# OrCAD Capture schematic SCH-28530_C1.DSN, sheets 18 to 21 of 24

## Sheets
18 18 PCIe: size C
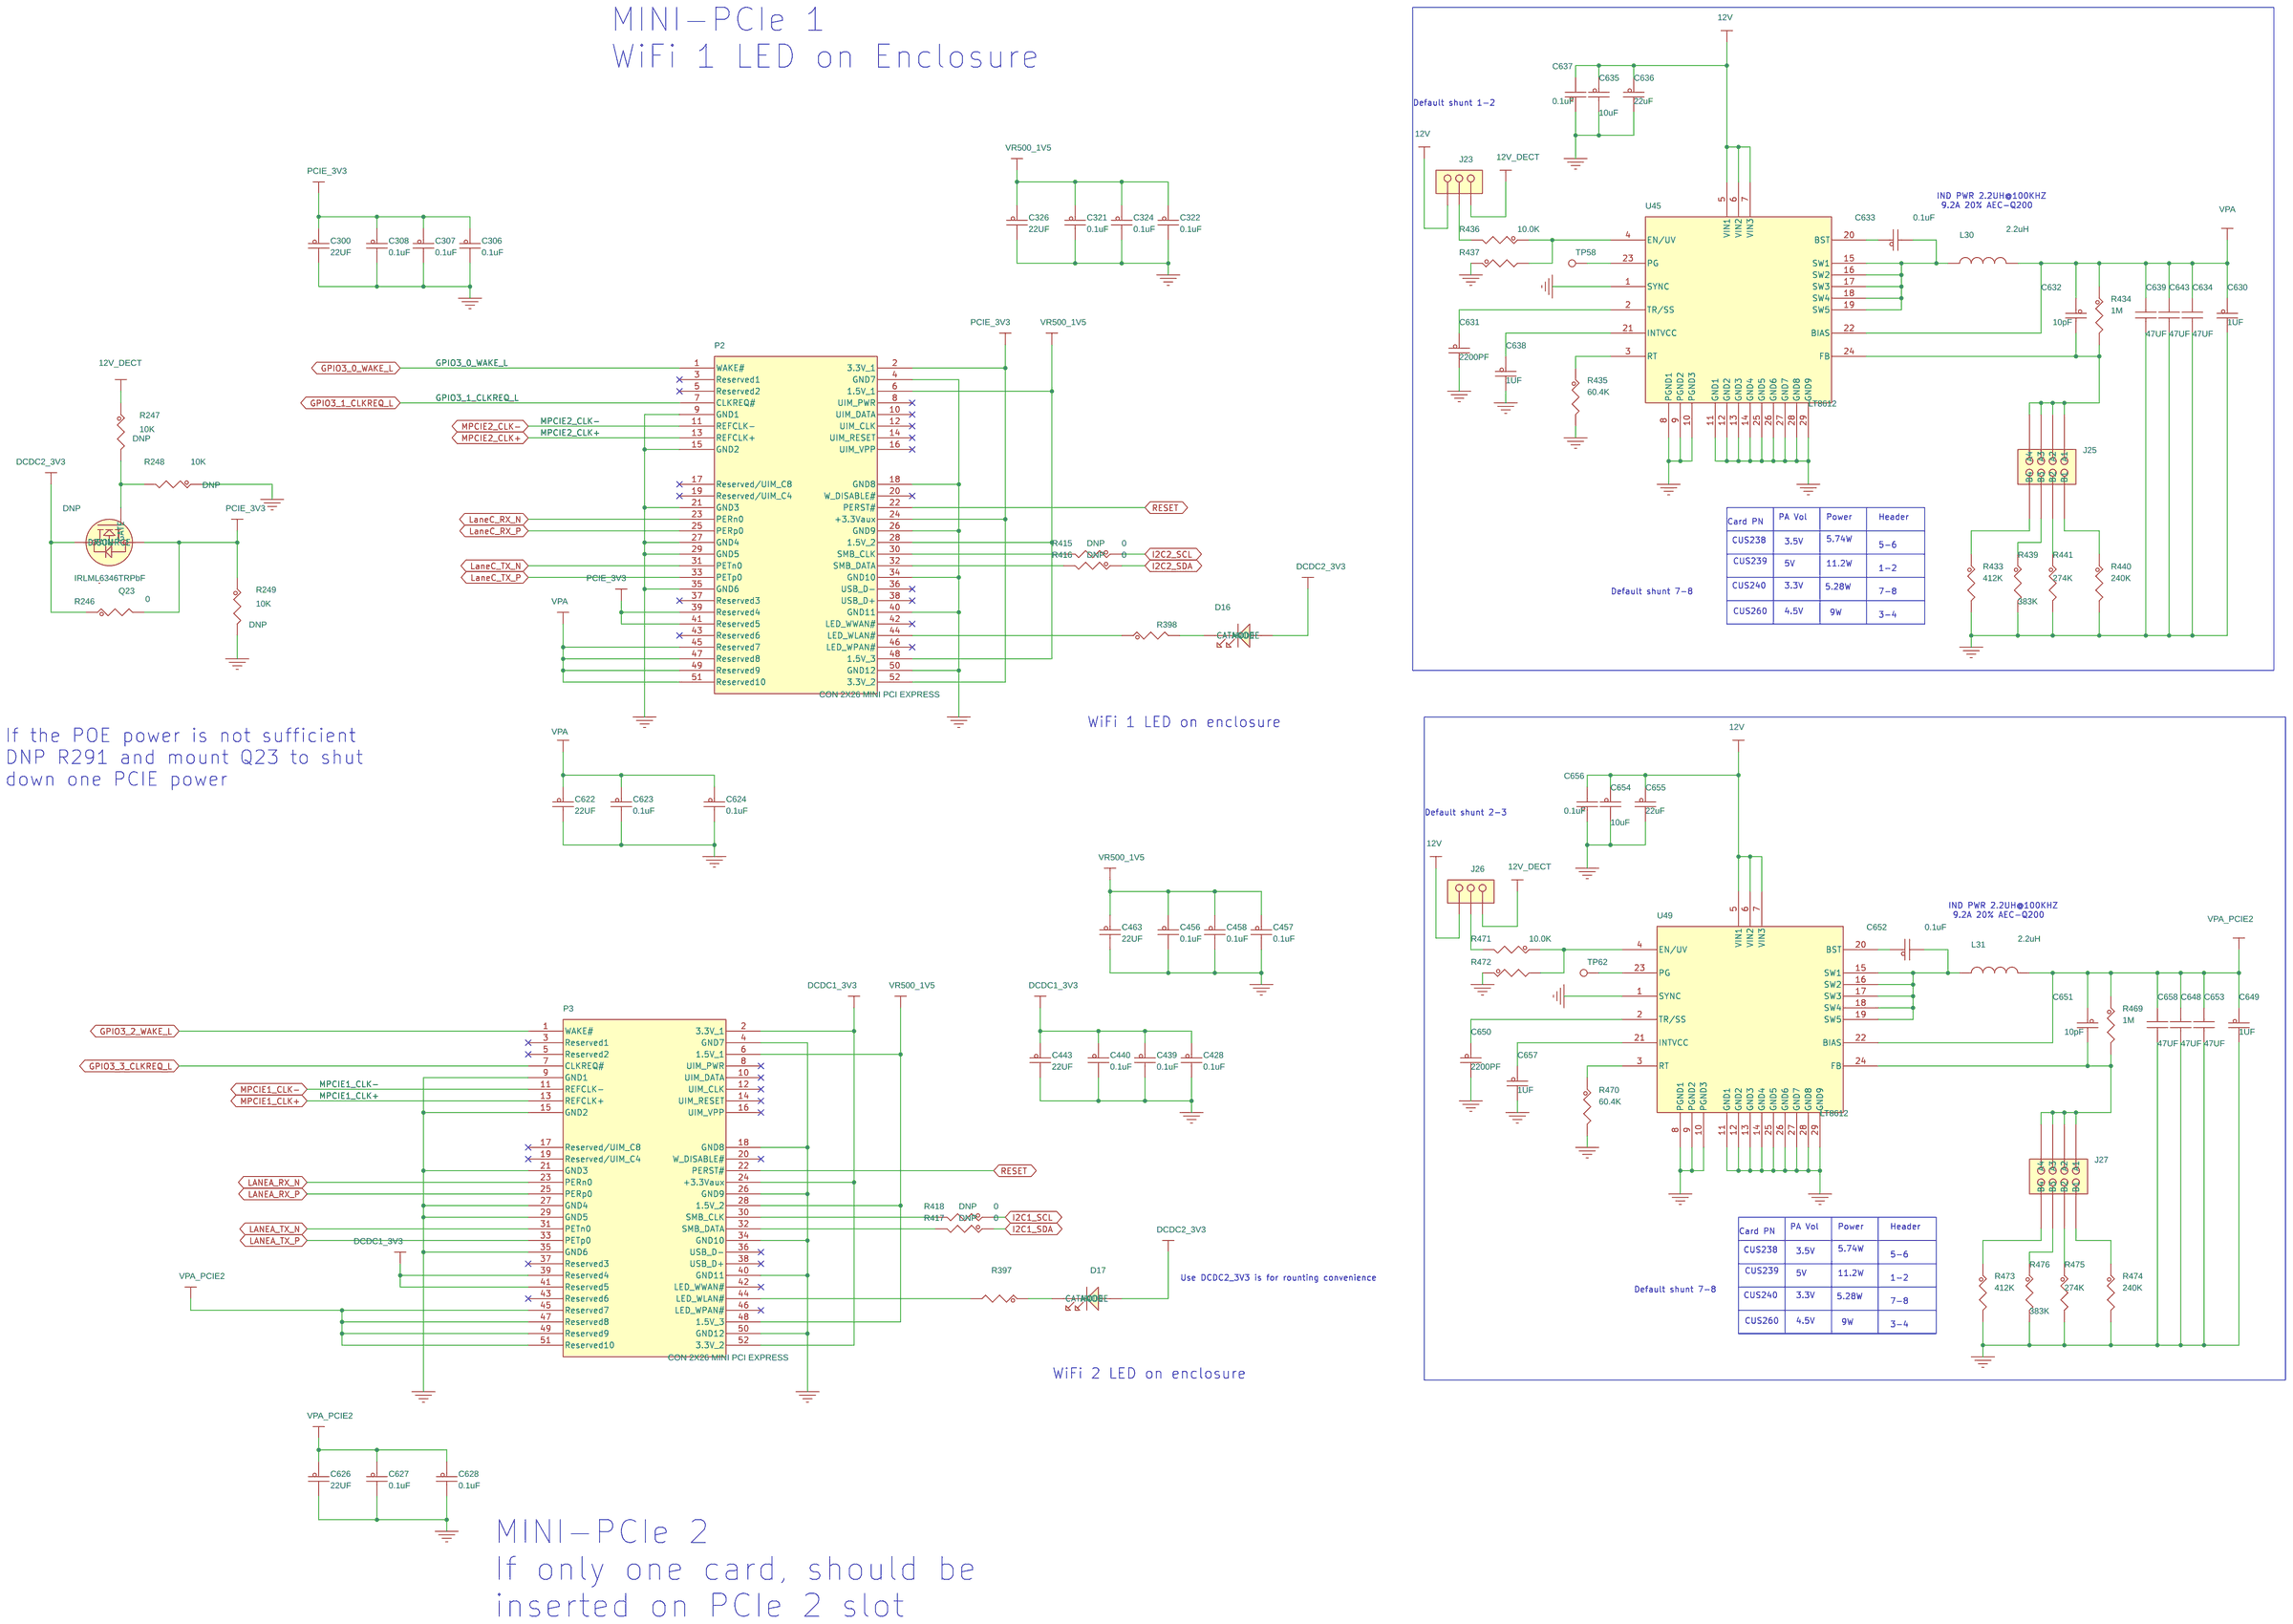
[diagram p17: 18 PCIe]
19 19 Clock: size C
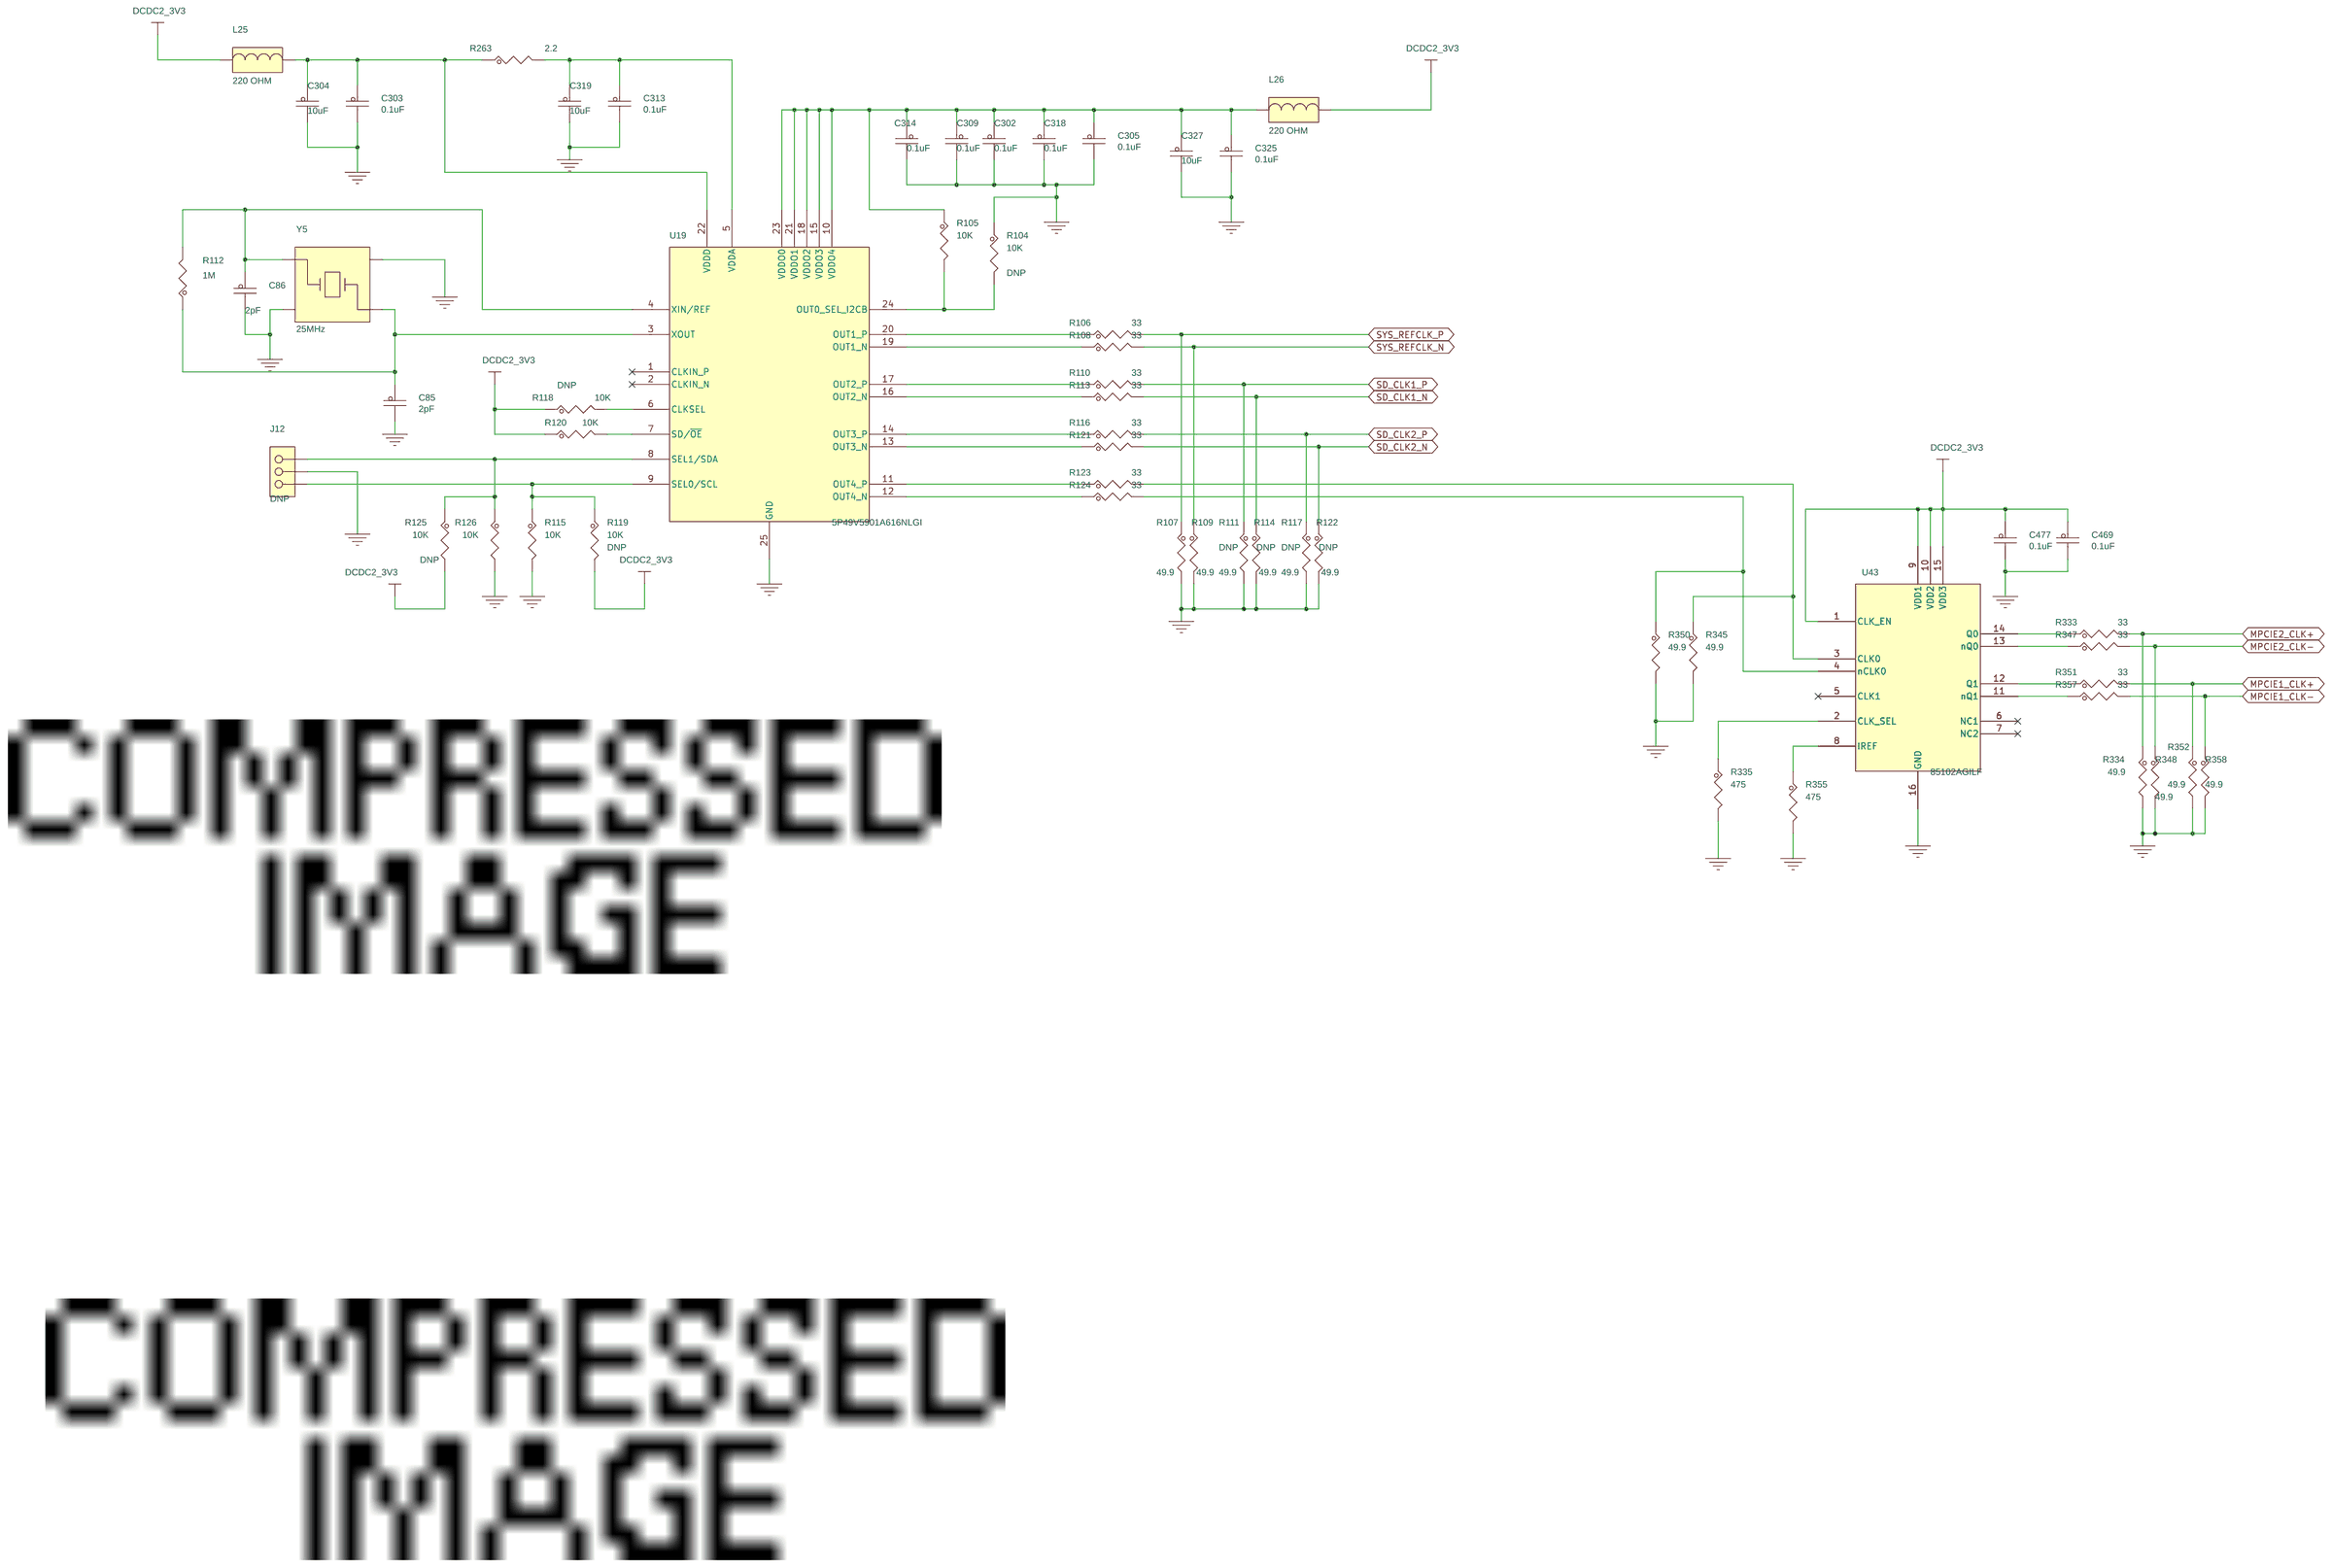
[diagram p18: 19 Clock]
20 22 CORE&S1VDD&3V3: size C
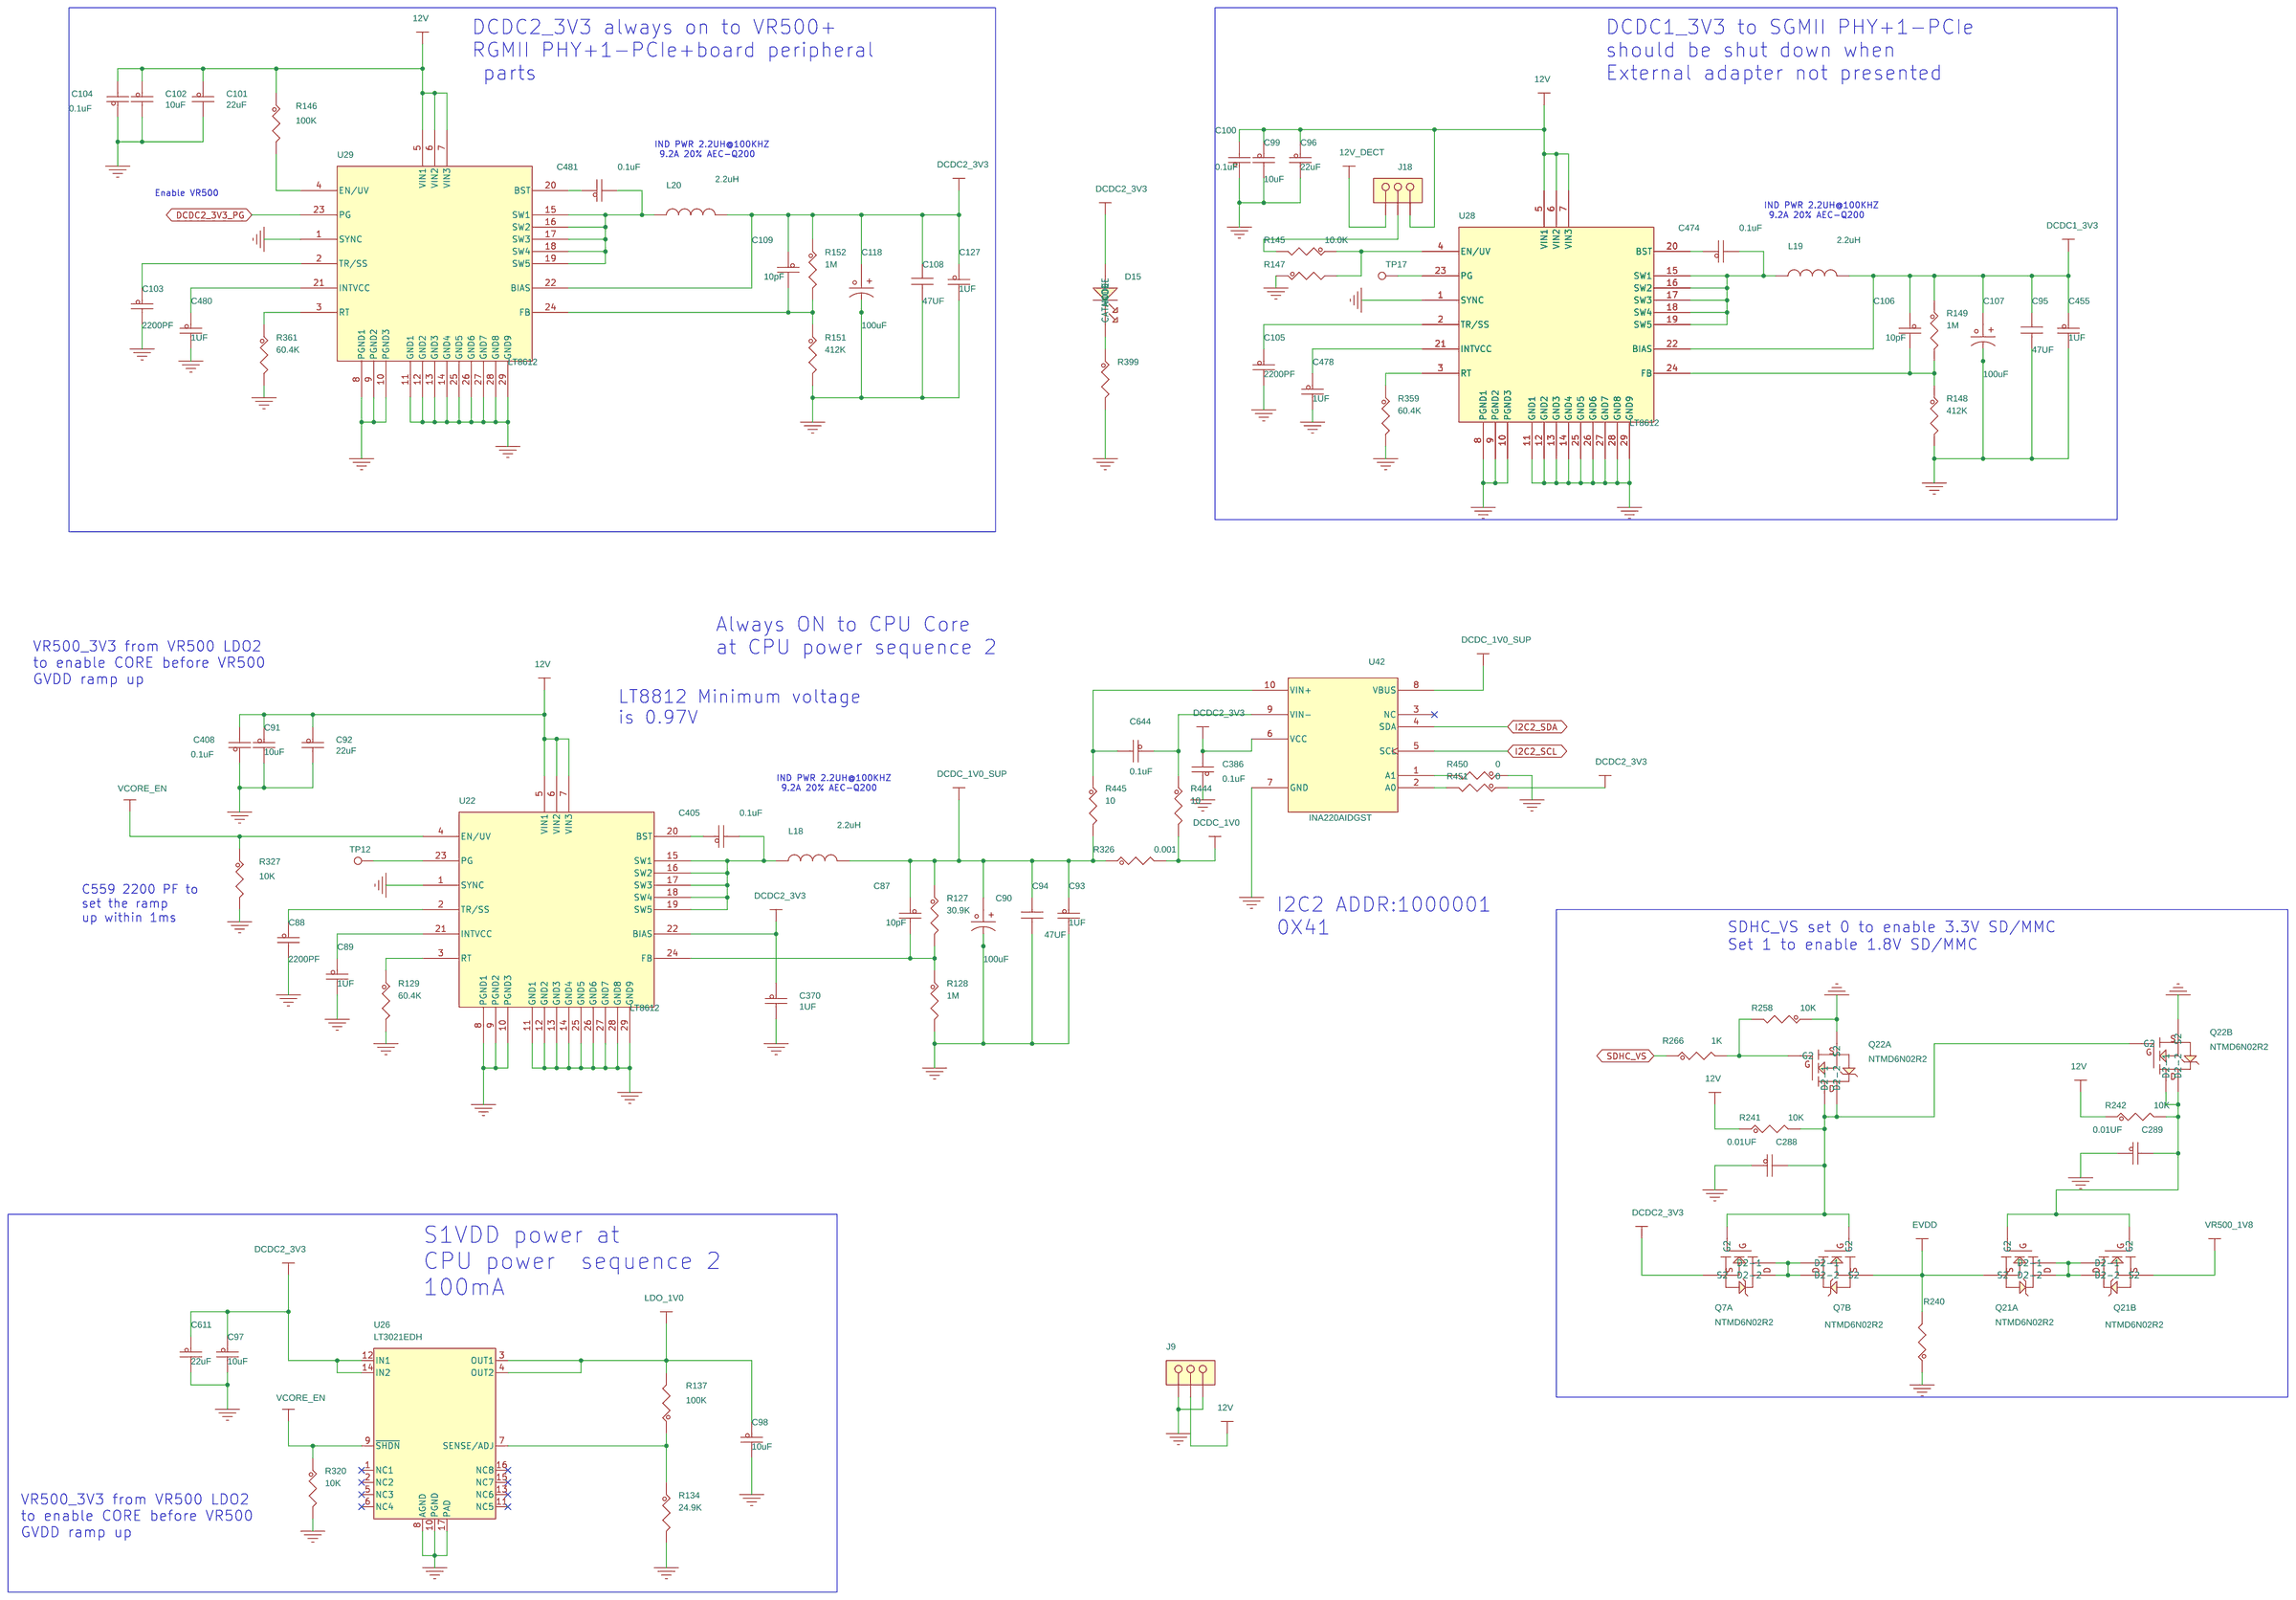
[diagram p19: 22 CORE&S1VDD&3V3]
21 23 12V POWER&RESET: size C
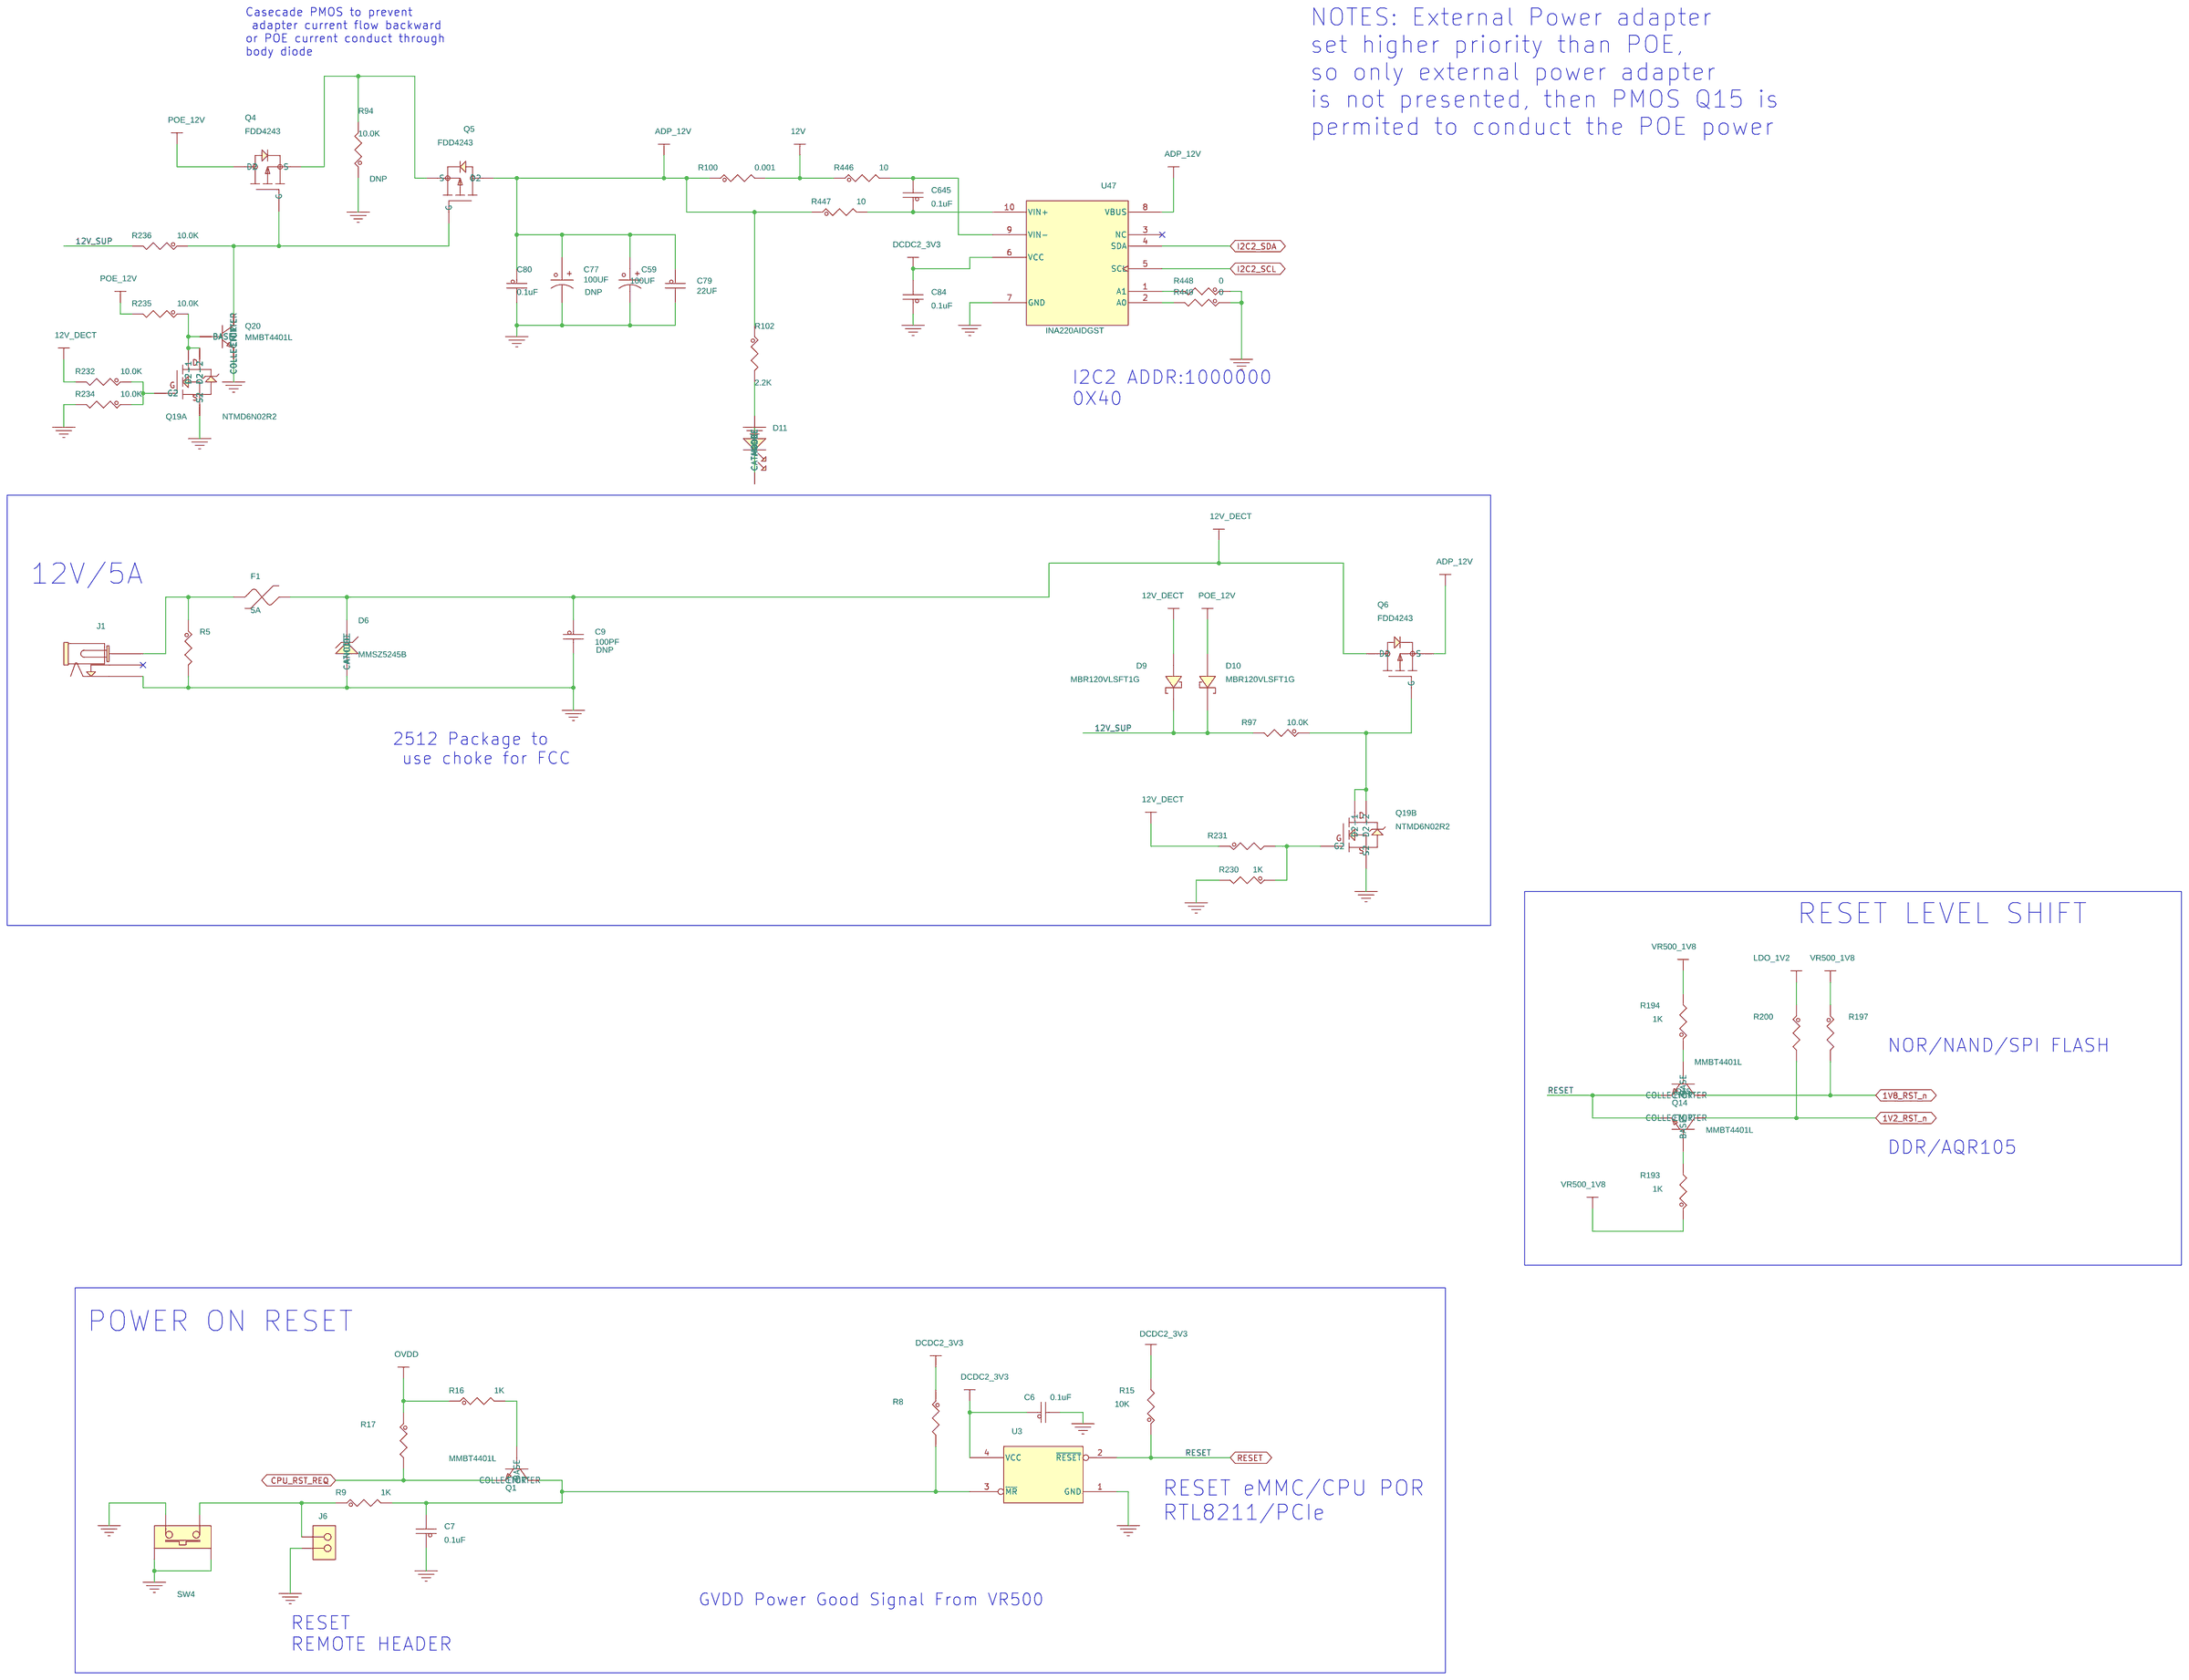
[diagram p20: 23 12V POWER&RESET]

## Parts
sheet 18 PCIe
C300  22UF  [CC0805_OV]
C306  0.1uF  [CC0402_25]
C307  0.1uF  [CC0402_25]
C308  0.1uF  [CC0402_25]
C321  0.1uF  [CC0402_25]
C322  0.1uF  [CC0402_25]
C324  0.1uF  [CC0402_25]
C326  22UF  [CC0805_OV]
C428  0.1uF  [CC0402_25]
C439  0.1uF  [CC0402_25]
C440  0.1uF  [CC0402_25]
C443  22UF  [CC0805_OV]
C456  0.1uF  [CC0402_25]
C457  0.1uF  [CC0402_25]
C458  0.1uF  [CC0402_25]
C463  22UF  [CC0805_OV]
C622  22UF  [CC0805_OV]
C623  0.1uF  [CC0402_25]
C624  0.1uF  [CC0402_25]
C626  22UF  [CC0805_OV]
C627  0.1uF  [CC0402_25]
C628  0.1uF  [CC0402_25]
C630  1UF  [CC0603_OV]
C631  2200PF  [CC0603_OV]
C632  10pF  [CC0402_25]
C633  0.1uF  [CC0402_25]
C634  47UF  [CC1210]
C635  10uF  [CC0603_OV]
C636  22uF  [CC0805_OV]
C637  0.1uF  [CC0402_25]
C638  1UF  [CC0603_OV]
C639  47UF  [CC1210]
C643  47UF  [CC1210]
C648  47UF  [CC1210]
C649  1UF  [CC0603_OV]
C650  2200PF  [CC0603_OV]
C651  10pF  [CC0402_25]
C652  0.1uF  [CC0402_25]
C653  47UF  [CC1210]
C654  10uF  [CC0603_OV]
C655  22uF  [CC0805_OV]
C656  0.1uF  [CC0402_25]
C657  1UF  [CC0603_OV]
C658  47UF  [CC1210]
D16  LED_GRN  [led2_2p54_6p6x4p3mm]
D17  LED_GRN  [led2_2p54_6p6x4p3mm]
J23  HDR_1X3  [hdr1x3_50mil]
J25  HDR_2X4  [hdr2x4_50mil]
J26  HDR_1X3  [hdr1x3_50mil]
J27  HDR_2X4  [hdr2x4_50mil]
L30  2.2uH  [ind2_xal50xx_222]
L31  2.2uH  [ind2_xal50xx_222]
P2  CON 2X26 MINI PCI EXPRESS  [con_2x26_0p8_smt]
P3  CON 2X26 MINI PCI EXPRESS  [con_2x26_0p8_smt]
Q23  IRLML6346TRPbF  [sot23-40x40]
R246  0  [RC0805_OV]
R247  10K  [RC0603_OV]
R248  10K  [RC0603_OV]
R249  10K  [RC0603_OV]
R397  330  [RC0603_OV]
R398  330  [RC0603_OV]
R415  0  [RC0402_25]
R416  0  [RC0402_25]
R417  0  [RC0402_25]
R418  0  [RC0402_25]
R433  412K  [RC0402_25]
R434  1M  [RC0402_25]
R435  60.4K  [RC0402_25]
R436  10.0K  [RC0603_OV]
R437  4.7K  [RC0402_25]
R439  383K  [RC0402_25]
R440  240K  [RC0402_25]
R441  274K  [RC0402_25]
R469  1M  [RC0402_25]
R470  60.4K  [RC0402_25]
R471  10.0K  [RC0603_OV]
R472  4.7K  [RC0402_25]
R473  412K  [RC0402_25]
R474  240K  [RC0402_25]
R475  274K  [RC0402_25]
R476  383K  [RC0402_25]
TP58  35 MIL  [TESTPOINT_35MIL]
TP62  35 MIL  [TESTPOINT_35MIL]
U45  LT8612  [qfn28_3x6_0p5]
U49  LT8612  [qfn28_3x6_0p5]
sheet 19 Clock
C85  2pF  [CC0402_25]
C86  2pF  [CC0402_25]
C302  0.1uF  [CC0402_25]
C303  0.1uF  [CC0402_25]
C304  10uF  [CC0603_OV]
C305  0.1uF  [CC0402_25]
C309  0.1uF  [CC0402_25]
C313  0.1uF  [CC0402_25]
C314  0.1uF  [CC0402_25]
C318  0.1uF  [CC0402_25]
C319  10uF  [CC0603_OV]
C325  0.1uF  [CC0402_25]
C327  10uF  [CC0603_OV]
C469  0.1uF  [CC0402_25]
C477  0.1uF  [CC0402_25]
J12  HDR TH 1X3  [HDR103]
L25  220 OHM  [IND_0603]
L26  220 OHM  [IND_0603]
R104  10K  [RC0603_OV]
R105  10K  [RC0603_OV]
R106  33  [RC0603_OV]
R107  49.9  [RC0603_OV]
R108  33  [RC0603_OV]
R109  49.9  [RC0603_OV]
R110  33  [RC0603_OV]
R111  49.9  [RC0603_OV]
R112  1M  [RC0402_25]
R113  33  [RC0603_OV]
R114  49.9  [RC0603_OV]
R115  10K  [RC0603_OV]
R116  33  [RC0603_OV]
R117  49.9  [RC0603_OV]
R118  10K  [RC0603_OV]
R119  10K  [RC0603_OV]
R120  10K  [RC0603_OV]
R121  33  [RC0603_OV]
R122  49.9  [RC0603_OV]
R123  33  [RC0603_OV]
R124  33  [RC0603_OV]
R125  10K  [RC0603_OV]
R126  10K  [RC0603_OV]
R263  2.2  [RC0402_25]
R333  33  [RC0603_OV]
R334  49.9  [RC0603_OV]
R335  475  [RC0603_OV]
R345  49.9  [RC0603_OV]
R347  33  [RC0603_OV]
R348  49.9  [RC0603_OV]
R350  49.9  [RC0603_OV]
R351  33  [RC0603_OV]
R352  49.9  [RC0603_OV]
R355  475  [RC0603_OV]
R357  33  [RC0603_OV]
R358  49.9  [RC0603_OV]
U19  5P49V5901A616NLGI  [qfn24_0p5_4x4_ep2p2]
U43  85102AGILF  [tssop16]
Y5  25MHz  [xtal4_3p3x2p6_sm_fl]
sheet 22 CORE&S1VDD&3V3
C87  10pF  [CC0402_25]
C88  2200PF  [CC0603_OV]
C89  1UF  [CC0603_OV]
C90  100uF  [cce63x55]
C91  10uF  [CC0603_OV]
C92  22uF  [CC0805_OV]
C93  1UF  [CC0603_OV]
C94  47UF  [CC1210]
C95  47UF  [CC1210]
C96  22uF  [CC0805_OV]
C97  10uF  [CC0603_OV]
C98  10uF  [CC0603_OV]
C99  10uF  [CC0603_OV]
C100  0.1uF  [CC0402_25]
C101  22uF  [CC0805_OV]
C102  10uF  [CC0603_OV]
C103  2200PF  [CC0603_OV]
C104  0.1uF  [CC0402_25]
C105  2200PF  [CC0603_OV]
C106  10pF  [CC0402_25]
C107  100uF  [cce63x55]
C108  47UF  [CC1210]
C109  10pF  [CC0402_25]
C118  100uF  [cce63x55]
C127  1UF  [CC0603_OV]
C288  0.01UF  [CC0402_25]
C289  0.01UF  [CC0402_25]
C370  1UF  [CC0402_25]
C386  0.1uF  [CC0402_25]
C405  0.1uF  [CC0402_25]
C408  0.1uF  [CC0402_25]
C455  1UF  [CC0603_OV]
C474  0.1uF  [CC0402_25]
C478  1UF  [CC0603_OV]
C480  1UF  [CC0603_OV]
C481  0.1uF  [CC0402_25]
C611  22uF  [CC0805_OV]
C644  0.1uF  [CC0402_25]
D15  LED_GRN  [led2_2p54_6p6x4p3mm]
J9  HDR TH 1X3  [HDR103]
J18  HDR_1X3  [hdr1x3_50mil]
L18  2.2uH  [ind2_xal50xx_222]
L19  2.2uH  [ind2_xal50xx_222]
L20  2.2uH  [ind2_xal50xx_222]
Q7  NTMD6N02R2  [SO8]  (sections A,B)
Q21  NTMD6N02R2  [SO8]  (sections A,B)
Q22  NTMD6N02R2  [SO8]  (sections A,B)
R127  30.9K  [RC0603_OV]
R128  1M  [RC0402_25]
R129  60.4K  [RC0402_25]
R134  24.9K  [RC0402_25]
R137  100K  [RC0603_OV]
R145  10.0K  [RC0603_OV]
R146  100K  [RC0603_OV]
R147  4.7K  [RC0402_25]
R148  412K  [RC0402_25]
R149  1M  [RC0402_25]
R151  412K  [RC0402_25]
R152  1M  [RC0402_25]
R240  4.7K  [RC0402_25]
R241  10K  [RC0603_OV]
R242  10K  [RC0603_OV]
R258  10K  [RC0603_OV]
R266  1K  [RC0603_OV]
R320  10K  [RC0603_OV]
R326  0.001  [RC1206_OV]
R327  10K  [RC0603_OV]
R359  60.4K  [RC0402_25]
R361  60.4K  [RC0402_25]
R399  330  [RC0603_OV]
R444  10  [RC0603_OV]
R445  10  [RC0603_OV]
R450  0  [RC0402_25]
R451  0  [RC0402_25]
TP12  35 MIL  [TESTPOINT_35MIL]
TP17  35 MIL  [TESTPOINT_35MIL]
U22  LT8612  [qfn28_3x6_0p5]
U26  LT3021EDH  [EDFN16_0P5_5X5_3P45X4P1]
U28  LT8612  [qfn28_3x6_0p5]
U29  LT8612  [qfn28_3x6_0p5]
U42  INA220AIDGST  [MSOP_10_0P5_3X3]
sheet 23 12V POWER&RESET
C6  0.1uF  [CC0402_25]
C7  0.1uF  [CC0402_25]
C9  100PF  [CC0603_OV]
C59  100UF  [cce63x55]
C77  100UF  [cce63x55]
C79  22UF  [CC1210]
C80  0.1uF  [CC0402_25]
C84  0.1uF  [CC0402_25]
C645  0.1uF  [CC0402_25]
D6  MMSZ5245B  [sod123]
D9  MBR120VLSFT1G  [SOD-123]
D10  MBR120VLSFT1G  [SOD-123]
D11  LED_GRN_DL  [LED_0603]
F1  5A  [fuse_hold_10p4x3_th]
J1  CONN PWR 1  [con3_pwr_jack]
J6  HDR 1X2  [HDR102]
Q1  MMBT4401L  [SOT23]
Q4  FDD4243  [to252aa]
Q5  FDD4243  [to252aa]
Q6  FDD4243  [to252aa]
Q14  MMBT4401L  [SOT23]
Q15  MMBT4401L  [SOT23]
Q19  NTMD6N02R2  [SO8]  (sections A,B)
Q20  MMBT4401L  [SOT23]
R5  10.0K  [RC0603_OV]
R8  4.7K  [RC0402_25]
R9  1K  [RC0603_OV]
R15  10K  [RC0603_OV]
R16  1K  [RC0603_OV]
R17  4.7K  [RC0402_25]
R94  10.0K  [RC0603_OV]
R97  10.0K  [RC0603_OV]
R100  0.001  [RC1206_OV]
R102  2.2K  [RC0603_OV]
R193  1K  [RC0603_OV]
R194  1K  [RC0603_OV]
R197  4.7K  [RC0402_25]
R200  4.7K  [RC0402_25]
R230  1K  [RC0603_OV]
R231  4.7K  [RC0402_25]
R232  10.0K  [RC0603_OV]
R234  10.0K  [RC0603_OV]
R235  10.0K  [RC0603_OV]
R236  10.0K  [RC0603_OV]
R446  10  [RC0603_OV]
R447  10  [RC0603_OV]
R448  0  [RC0402_25]
R449  0  [RC0402_25]
SW4  TL1105NF160Q  [sw_4p_7p1x15p8]
U3  MAX811  [SOT143-25X60]
U47  INA220AIDGST  [MSOP_10_0P5_3X3]

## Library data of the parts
C300 C443 C622 C626 = CAP_NP: CAP CER 22UF 6.3V 20% X5R 0805; AGILE_PN: 150-30121; CAD_APPROVED: Yes; FPLIST: CC0805_OV,CC0805,0805_CC; HEIGHT: 1.45MM; MFG_NAME01: MURATA; MFG_PN01: GRM21BR60J226ME39L; ROHS: Yes; SIGNAL_MODEL: CAP_NP_CC0402_25_0_55MM_150_762_0_01uF; TOL: 20%; Tolerance: 20%; VOLTAGE: 6.3V
C306 C428 C624 C628 = CAP_NP: CAP CER 0.1UF 25V 10% X5R 0402; AGILE_PN: 150-78633; CAD_APPROVED: Yes; FPLIST: CC0402_25,CC0402_HD,0402_CC; HEIGHT: 0.55MM; MFG_NAME01: YAGEO AMERICA; MFG_PN01: CC0402KRX5R8BB104; ROHS: Yes; SIGNAL_MODEL: DEFAULT_CAPACITOR_1e+06pF_2_1; TOL: 10%; Tolerance: 10%; VOLTAGE: 25V
C307 C324 C439 C458 = CAP_NP: CAP CER 0.1UF 25V 10% X5R 0402; AGILE_PN: 150-78633; CAD_APPROVED: Yes; FPLIST: CC0402_25,CC0402_HD,0402_CC; HEIGHT: 0.55MM; MFG_NAME01: YAGEO AMERICA; MFG_PN01: CC0402KRX5R8BB104; ROHS: Yes; SIGNAL_MODEL: DEFAULT_CAPACITOR_1e+07pF_2_1; TOL: 10%; Tolerance: 10%; VOLTAGE: 25V
C308 C321 C322 C440 C456 C457 C623 C627 = CAP_NP: CAP CER 0.1UF 25V 10% X5R 0402; AGILE_PN: 150-78633; CAD_APPROVED: Yes; FPLIST: CC0402_25,CC0402_HD,0402_CC; HEIGHT: 0.55MM; MFG_NAME01: YAGEO AMERICA; MFG_PN01: CC0402KRX5R8BB104; ROHS: Yes; SIGNAL_MODEL: CAP_NP_CC0402_25_0_55MM_150_762_0_01uF; TOL: 10%; Tolerance: 10%; VOLTAGE: 25V
C326 C463 = CAP_NP: CAP CER 22UF 6.3V 20% X5R 0805; AGILE_PN: 150-30121; CAD_APPROVED: Yes; FPLIST: CC0805_OV,CC0805,0805_CC; HEIGHT: 1.45MM; MFG_NAME01: MURATA; MFG_PN01: GRM21BR60J226ME39L; ROHS: Yes; SIGNAL_MODEL: DEFAULT_CAPACITOR_1e+06pF_2_1; TOL: 20%; Tolerance: 20%; VOLTAGE: 6.3V
C89 C93 C127 C455 C478 C480 C630 C638 C649 C657 = CAP_NP: CAP CER 1uF 25V 10% X7R AEC-Q200 0603; AGILE_PN: 150-79081; CAD_APPROVED: Yes; FPLIST: CC0603_OV,CC0603,0603_CC; HEIGHT: 0.9MM; MFG_NAME01: TDK; MFG_PN01: CGA3E1X7R1E105K080AC; ROHS: Yes; Tolerance: 10%; VOLTAGE: 25V
C88 C103 C105 C631 C650 = CAP_NP: CAP CER 2200PF 50V 5% X7R 0603; AGILE_PN: 150-77306; CAD_APPROVED: Yes; FPLIST: CC0603_OV,CC0603,0603_CC; HEIGHT: 0.87MM; MFG_NAME01: KEMET; MFG_PN01: C0603C222J5RACTU; ROHS: Yes; Tolerance: 5%; VOLTAGE: 50V
C87 C106 C109 C632 C651 = CAP_NP: CAP CER 10pF 50V 2% C0G 0402; AGILE_PN: 150-78893; CAD_APPROVED: Yes; FPLIST: CC0402_25,CC0402_HD,0402_CC; HEIGHT: 0.55 MM; MFG_NAME01: MURATA; MFG_PN01: GJM1555C1H100GB01D; ROHS: Yes; Tolerance: 2%; VOLTAGE: 50V
C100 C104 C405 C408 C474 C481 C633 C637 C652 C656 = CAP_NP: CAP CER 0.1uF 16V 10% X7R AEC-Q200 0402; AGILE_PN: 150-79025; CAD_APPROVED: Yes; FPLIST: CC0402_25,CC0402_HD,0402_CC; HEIGHT: 0.55MM; MFG_NAME01: MURATA; MFG_PN01: GCM155R71C104KA55D; ROHS: Yes
C94 C95 C108 C634 C639 C643 C648 C653 C658 = MOT_CAP: CAP CER 47UF 16V 10% X5R 1210; AGILE_PN: 150-75908; CAD_APPROVED: Yes; FPLIST: CC1210,1210_CC; HEIGHT: 2.7 mm; MFG_NAME01: MURATA; MFG_PN01: GRM32ER61C476KE15L; ROHS: Yes; Tolerance: 10%; VOLTAGE: 16V
C91 C97-C99 C102 C304 C319 C327 C635 C654 = CAP_NP: CAP CER 10uF 25V 20% X5R 0603; AGILE_PN: 150-79272; CAD_APPROVED: Yes; FPLIST: CC0603_OV,CC0603,0603_CC; HEIGHT: 1MM; MFG_NAME01: Murata; MFG_PN01: GRM188R61E106MA73D; ROHS: Yes; Tolerance: 20%; VOLTAGE: 25V
C92 C96 C101 C611 C636 C655 = CAP_NP: CAP CER 22uF 25V 20% X5R 0805; AGILE_PN: 150-79304; FPLIST: CC0805_OV,CC0805,0805_CC; HEIGHT: 1.45MM; MFG_NAME01: MURATA; MFG_PN01: GRM21BR61E226ME44; ROHS: Yes; Tolerance: 20%; VOLTAGE: 25V
D15-D17 = LED: LED GRN SGL RA 25MA TH; AGILE_PN: 370-76483; CAD_APPROVED: Yes; HEIGHT: 7.55MM; MFG_NAME01: KINGBRIGHT; MFG_PN01: L-7104EW/1GD-SH; ROHS: Yes
J18 J23 J26 = CONN_HDR_3X1: HDR 1X3 TH 50MIL SP 165H AU 91L; AGILE_PN: 210-80213; CAD_APPROVED: Yes; HEIGHT: 4.2MM; MFG_NAME01: SULLINS ELECTRONICS CORP; MFG_PN01: GRPB031VWVN-RC; ROHS: Yes
J25 J27 = CONN_HDR_4X2: HDR 2X4 TH 50MIL CTR 165H AU 91L; AGILE_PN: 210-80214; CAD_APPROVED: Yes; HEIGHT: 4.2MM; MFG_NAME01: SULLINS ELECTRONICS CORP; MFG_PN01: GRPB042VWVN-RC; ROHS: Yes
L18-L20 L30 L31 = INDUCTOR: IND PWR 2.2UH@100KHZ 9.2A 20% AEC-Q200 SMT; AGILE_PN: 180-78148; CAD_APPROVED: Yes; HEIGHT: 3.1MM; MFG_NAME01: coilcraft; MFG_PN01: XAL5030-222MEB; PART_TYPE: INDUCTOR\POWER; ROHS: Yes; Tolerance: 20%
P2 P3 = MINI_PCI_LATCH_52P: CON 2X26 MINI PCI EXPRESS SMT 0.8MM SP 1136H; AGILE_PN: 211-78711; CAD_APPROVED: Yes; FPLIST: con_2x26_0p8_smt,con_2x26_0p8_smt_nsp; HEIGHT: 28.85MM; MFG_NAME01: Molex; MFG_PN01: 679100002; ROHS: Yes
Q23 = MOSFET_N: TRAN NMOS PWR 3.4A 30V SOT-23; AGILE_PN: 480-78399; ASSY_OPT: DNP; CAD_APPROVED: Yes; HEIGHT: 1.12 MM; MFG_NAME01: International Rectifier; ROHS: Yes
R246 = RES: RES MF ZERO OHM 1/8W -- 0805; AGILE_PN: 470-75442; CAD_APPROVED: Yes; FPLIST: RC0805_OV,RC0805,RC0805_OV_3P,0805_CC; HEIGHT: 0.7 MM; MFG_NAME01: YAGEO AMERICA; MFG_PN01: RC0805JR-070RL; ROHS: Yes; Tolerance: 5%
R104 R118 R119 R125 R247-R249 = RES: RES MF 10K 1/10W 5% 0603; AGILE_PN: 470-75410; ASSY_OPT: DNP; CAD_APPROVED: Yes; FPLIST: RC0603_OV,RC0603,0603_CC; HEIGHT: 0.55MM; MFG_NAME01: KOA SPEER; MFG_PN01: RK73B1JTTD103J; ROHS: Yes; Tolerance: 5%
R397-R399 = RES: RES MF 330 OHM 1/10W 1% 0603; AGILE_PN: 470-75512; CAD_APPROVED: Yes; FPLIST: RC0603_OV,RC0603,0603_CC; HEIGHT: 0.55 MM; MFG_NAME01: KOA SPEER; MFG_PN01: RK73H1JTTD3300F; ROHS: Yes; SIGNAL_MODEL: DEFAULT_RESISTOR_330OHM_2_1; TOL: 1%; Tolerance: 1%
R415-R418 = RES: RES MF ZERO OHM 1/16W 5% 0402; AGILE_PN: 470-75394; ASSY_OPT: DNP; CAD_APPROVED: Yes; FPLIST: RC0402_25,RC0402_HD,RC0402_X2,0402_CC; HEIGHT: 0.45 MM; MFG_NAME01: ROHM; MFG_PN01: MCR01MZPJ000; ROHS: Yes; SIGNAL_MODEL: RES_RC0402_25_DISCRETE_470-7539_0; Tolerance: 5%
R148 R151 R433 R473 = RES: RES MF 412K 1/16W 1% AEC-Q200 0402; AGILE_PN: 470-31129; CAD_APPROVED: Yes; FPLIST: RC0402_25,RC0402_HD,0402_CC; HEIGHT: 0.40 MM; MFG_NAME01: VISHAY INTERTECHNOLOGY; MFG_PN01: CRCW0402412KFKED; ROHS: Yes; Tolerance: 1%
R128 R149 R152 R434 R469 = RES: RES MF 1.0M 1/16W 1% AEC-Q200 0402; AGILE_PN: 470-30000; CAD_APPROVED: Yes; FPLIST: RC0402_25,RC0402_HD,0402_CC; HEIGHT: 0.4MM; MFG_NAME01: VISHAY INTERTECHNOLOGY; MFG_PN01: CRCW04021M00FKED; ROHS: Yes; Tolerance: 1%
R129 R359 R361 R435 R470 = RES: RES MF 60.4K  1/16W 1% 0402; AGILE_PN: 470-31036; CAD_APPROVED: Yes; FPLIST: RC0402_25,RC0402_HD,0402_CC; HEIGHT: 0.40 MM; MFG_NAME01: KOA SPEER; MFG_PN01: RK73H1ETTP6042F; ROHS: Yes; Tolerance: 1%
R97 R145 R232 R234-R236 R436 R471 = RES: RES MF 10.0K 1/10W 1% 0603; AGILE_PN: 470-75422; CAD_APPROVED: Yes; FPLIST: RC0603_OV,RC0603,0603_CC; HEIGHT: 0.6MM; MFG_NAME01: KOA SPEER; MFG_PN01: RK73H1JTTD1002F; ROHS: Yes; Tolerance: 1%
R8 R17 R147 R197 R200 R231 R437 R472 = RES: RES MF 4.7K 1/16W 5% 0402; AGILE_PN: 470-75626; CAD_APPROVED: Yes; FPLIST: RC0402_25,RC0402_HD,0402_CC; Function: UART; HEIGHT: 0.41mm; MFG_NAME01: KOA SPEER; MFG_PN01: RK73B1ETTP472J; ROHS: Yes; SIGNAL_MODEL: DEFAULT_RESISTOR_4700OHM_2_1; TOL: 5%; Tolerance: 5%
R439 R476 = RES: RES MF 383K  1/16W 1% 0402; AGILE_PN: 470-31125; CAD_APPROVED: Yes; FPLIST: RC0402_25,RC0402_HD,0402_CC; HEIGHT: 0.4 MM; MFG_NAME01: KOA SPEER; MFG_PN01: RK73H1ETTP3833F; ROHS: Yes; Tolerance: 1%
R440 R474 = RES: RES TF 240K 1/16W 1% 0402; AGILE_PN: 470-76980; CAD_APPROVED: Yes; FPLIST: RC0402_25,RC0402_HD,0402_CC; HEIGHT: 0.4MM; MFG_NAME01: BOURNS; MFG_PN01: CR0402-FX-2403GLF; ROHS: Yes; Tolerance: 1%
R441 R475 = RES: RES MF 274K  1/16W 1% 0402; AGILE_PN: 470-31108; CAD_APPROVED: Yes; FPLIST: RC0402_25,RC0402_HD,0402_CC; HEIGHT: 0.40 MM; MFG_NAME01: KOA SPEER; MFG_PN01: RK73H1ETTP2743F; ROHS: Yes; Tolerance: 1%
TP12 TP17 TP58 TP62 = Test_pad: TEST PAD 35 MIL ROUND SMT; NO PART TO ORDER; AGILE_PN: 510-75219; CAD_APPROVED: Yes; HEIGHT: 0.1 MM; ROHS: Yes
U22 U28 U29 U45 U49 = LT8612_28P_QFN_EP: IC VREG BUCK ADJ 6A 3.4-42V QFN28; AGILE_PN: 315-80446; CAD_APPROVED: Yes; HEIGHT: 0.85MM; MFG_NAME01: LINEAR TECHNOLOGY; MFG_PN01: LT8612EUDE#PBF; ROHS: Yes
C85 C86 = CAP_NP: CAP CER 2pF 50V 13% C0G 0402; AGILE_PN: 150-78885; CAD_APPROVED: Yes; FPLIST: CC0402_25,CC0402_HD,0402_CC; HEIGHT: 0.55MM; MFG_NAME01: MURATA; MFG_PN01: GJM1555C1H2R0CB01D; ROHS: Yes; Tolerance: 13%; VOLTAGE: 50V
C6 C7 C84 C302 C303 C305 C309 C313 C314 C318 C325 C386 C469 C477 C644 C645 = CAP_NP: CAP CER 0.1UF 25V 10% X5R 0402; AGILE_PN: 150-78633; CAD_APPROVED: Yes; FPLIST: CC0402_25,CC0402_HD,0402_CC; HEIGHT: 0.55MM; MFG_NAME01: YAGEO AMERICA; MFG_PN01: CC0402KRX5R8BB104; ROHS: Yes; Tolerance: 10%; VOLTAGE: 25V
J12 = CONN_HDR_3X1: HDR 1X3 TH 100MIL SP 339H AU 100L; AGILE_PN: 210-75726; ASSY_OPT: DNP; CAD_APPROVED: Yes; HEIGHT: 8.65MM; MFG_NAME01: SAMTEC; MFG_PN01: TSW-103-07-G-S; ROHS: Yes
L25 L26 = BEAD: IND FER BEAD 220 OHM@100MHZ 0.45A 25% 0603; AGILE_PN: 180-77994; CAD_APPROVED: Yes; FPLIST: IND_0603,IND0603_CC; HEIGHT: 0.95MM; MFG_NAME01: Murata; MFG_PN01: BLM18BB221SN1B; PART_TYPE: FERRITE\BEAD; ROHS: Yes; Tolerance: 25%
R15 R105 R115 R120 R126 R241 R242 R258 R320 R327 = RES: RES MF 10K 1/10W 5% 0603; AGILE_PN: 470-75410; CAD_APPROVED: Yes; FPLIST: RC0603_OV,RC0603,0603_CC; HEIGHT: 0.55MM; MFG_NAME01: KOA SPEER; MFG_PN01: RK73B1JTTD103J; ROHS: Yes; Tolerance: 5%
R106 R108 R110 R113 R116 R121 R123 R124 R333 R347 R351 R357 = RES: RES MF 33 OHM 1/10W 1% 0603; AGILE_PN: 470-75389; CAD_APPROVED: Yes; FPLIST: RC0603_OV,RC0603,0603_CC; HEIGHT: 0.55 mm; MFG_NAME01: KOA SPEER; MFG_PN01: RK73H1JTTD33R0F; ROHS: Yes; Tolerance: 1%
R107 R109 R334 R345 R348 R350 R352 R358 = RES: RES MF 49.9 OHM 1/10W 1% 0603; AGILE_PN: 470-75432; CAD_APPROVED: Yes; FPLIST: RC0603_OV,RC0603,0603_CC; HEIGHT: 0.55 MM; MFG_NAME01: KOA SPEER; MFG_PN01: RK73H1JTTD49R9F; ROHS: Yes; Tolerance: 1%
R111 R114 R117 R122 = RES: RES MF 49.9 OHM 1/10W 1% 0603; AGILE_PN: 470-75432; ASSY_OPT: DNP; CAD_APPROVED: Yes; FPLIST: RC0603_OV,RC0603,0603_CC; HEIGHT: 0.55 MM; MFG_NAME01: KOA SPEER; MFG_PN01: RK73H1JTTD49R9F; ROHS: Yes; Tolerance: 1%
R112 = RES: RES MF 1M 1/16W 1% 0402; AGILE_PN: 470-80575; CAD_APPROVED: Yes; FPLIST: RC0402_25,RC0402_HD,0402_CC; HEIGHT: 0.4MM; MFG_NAME01: BOURNS; MFG_PN01: CR0402-FX-1004GLF; ROHS: Yes; Tolerance: 1%
R263 = RES: RES MF 2.20 OHM 1/16W 1% 0402; AGILE_PN: 470-76093; CAD_APPROVED: Yes; FPLIST: RC0402_25,RC0402_HD,0402_CC; HEIGHT: 0.4MM; MFG_NAME01: KOA SPEER; MFG_PN01: RK73H1ETTP2R20F; ROHS: Yes; Tolerance: 1%
R335 R355 = RES: RES MF 475 OHM 1/10W 1% 0603; AGILE_PN: 470-75540; CAD_APPROVED: Yes; FPLIST: RC0603_OV,RC0603,0603_CC; HEIGHT: 0.55 MM; MFG_NAME01: KOA SPEER; MFG_PN01: RK73H1JTTD4750F; ROHS: Yes; Tolerance: 1%
U19 = IDT5P49V5901_24P: IC CLK GEN VERSACLK5 1.71-3.465V VFQFPN24; AGILE_PN: TMP-WF-23432; CAD_APPROVED: Yes; HEIGHT: 1MM; MFG_NAME01: INTEGRATED DEVICE TECHNOLOGY (IDT); PRE_APN: 312-81083; ROHS: Yes
U43 = 85102AGI_TSSOP_16P: IC CLK BUF 1:2  3.3V TSSOP16; AGILE_PN: 312-81077; CAD_APPROVED: Yes; HEIGHT: 1.2MM; MFG_NAME01: INTEGRATED DEVICE TECHNOLOGY (IDT); ROHS: Yes
Y5 = XTAL_13Y: XTAL 25MHZ RSN 8pF SMT; AGILE_PN: 230-77947; CAD_APPROVED: Yes; HEIGHT: 0.75MM; MFG_NAME01: PERICOM SEMICONDUCTOR; MFG_PN01: FL2500094; ROHS: Yes
C90 C107 C118 = CAP_POL: CAP ALEL 100uF 16V 20% -- SMD; AGILE_PN: 150-78723; CAD_APPROVED: Yes; HEIGHT: 5.5MM; MFG_NAME01: LELON ELECTRONICS CORP; MFG_PN01: VE-101M1CTR-0605; ROHS: Yes; Tolerance: 20%; VOLTAGE: 16V
C288 C289 = CAP_NP: CAP CER 0.01UF 16V 20% X7R 0402; AGILE_PN: 150-30082; CAD_APPROVED: Yes; FPLIST: CC0402_25,CC0402_HD,0402_CC; HEIGHT: 0.56MM; MFG_NAME01: AVX; MFG_PN01: 0402YC103MAT2A; ROHS: Yes; Tolerance: 20%; VOLTAGE: 16V
C370 = CAP_NP: CAP CER 1UF 6.3V 20% X5R 0402; AGILE_PN: 150-78002; CAD_APPROVED: Yes; FPLIST: CC0402_25,CC0402_HD,0402_CC; HEIGHT: 0.55MM; MFG_NAME01: MURATA; MFG_PN01: GRM155R60J105ME19D; ROHS: Yes; Tolerance: 20%; VOLTAGE: 6.3V
J9 = CONN_HDR_3X1: HDR 1X3 TH 100MIL SP 339H AU 100L; AGILE_PN: 210-75726; CAD_APPROVED: Yes; HEIGHT: 8.65MM; MFG_NAME01: SAMTEC; MFG_PN01: TSW-103-07-G-S; ROHS: Yes
Q7 Q19 Q21 Q22 = MMDF4N01HD: TRAN NMOS PWR 20V 6A SO8; AGILE_PN: 312-30125; CAD_APPROVED: Yes; HEIGHT: 1.75 MM; MFG_NAME01: ON SEMICONDUCTOR; MFG_PN01: NTMD6N02R2G; ROHS: Yes
R127 = RES: RES MF 30.9K 1/10W 1% 0603; AGILE_PN: 470-78065; CAD_APPROVED: Yes; FPLIST: RC0603_OV,RC0603,0603_CC; HEIGHT: 0.55MM; MFG_NAME01: KOA SPEER; MFG_PN01: RK73H1JTTD3092F; ROHS: Yes; Tolerance: 1%
R134 = RES: RES MF 24.9K  1/16W 1% 0402; AGILE_PN: 470-30990; CAD_APPROVED: Yes; FPLIST: RC0402_25,RC0402_HD,0402_CC; HEIGHT: 0.40 MM; MFG_NAME01: KOA SPEER; MFG_PN01: RK73H1ETTP2492F; ROHS: Yes; Tolerance: 1%
R137 R146 = RES: RES MF 100K 1/10W 1% 0603; AGILE_PN: 470-75424; CAD_APPROVED: Yes; FPLIST: RC0603_OV,RC0603,0603_CC; HEIGHT: 0.6MM; MFG_NAME01: KOA SPEER; MFG_PN01: RK73H1JTTD1003F; ROHS: Yes; Tolerance: 1%
R240 = RES: RES MF 4.7K 1/16W 5% 0402; AGILE_PN: 470-75626; CAD_APPROVED: Yes; FPLIST: RC0402_25,RC0402_HD,0402_CC; HEIGHT: 0.41mm; ICA_MFR_NAME: <ICA_MFR_NAME>; MFG_NAME01: KOA SPEER; MFG_PN01: RK73B1ETTP472J; ROHS: Yes; SIGNAL_MODEL: DEFAULT_RESISTOR_33OHM_2_1; Tolerance: 5%
R9 R16 R193 R194 R230 R266 = RES: RES MF 1K 1/10W 1% 0603; AGILE_PN: 470-80784; CAD_APPROVED: Yes; FPLIST: RC0603_OV,RC0603,0603_CC; HEIGHT: 0.55MM; MFG_NAME01: VIKING TECH CORPORATION; MFG_PN01: AR03FTNX1001; ROHS: Yes; Tolerance: 1%
R100 R326 = RES: RES MF 0.001 OHM 1W 1% 1206; AGILE_PN: 470-79980; CAD_APPROVED: Yes; FPLIST: RC1206_OV,RC1206,1206_CC; HEIGHT: 0.9MM; MFG_NAME01: STACKPOLE ELECTRONICS; MFG_PN01: CSNL1206FT1L00; ROHS: Yes; Tolerance: 1%
R444-R447 = RES: RES MF 10 OHM 1/10W 5% 0603; AGILE_PN: 470-75847; CAD_APPROVED: Yes; FPLIST: RC0603_OV,RC0603,0603_CC; HEIGHT: 0.55MM; MFG_NAME01: KOA SPEER; MFG_PN01: RK73B1JTTD100J; ROHS: Yes; Tolerance: 5%
R448-R451 = RES: RES MF ZERO OHM 1/16W 5% 0402; AGILE_PN: 470-75394; CAD_APPROVED: Yes; FPLIST: RC0402_25,RC0402_HD,RC0402_X2,0402_CC; HEIGHT: 0.45 MM; MFG_NAME01: ROHM; MFG_PN01: MCR01MZPJ000; ROHS: Yes; SIGNAL_MODEL: RES_RC0402_25_DISCRETE_470-7539_0; Tolerance: 5%
U26 = LT3021: IC REG ADJ 0.9V TO 10V 500MA; AGILE_PN: 312-75595; CAD_APPROVED: Yes; HEIGHT: 0.8MM; MFG_NAME01: LINEAR TECHNOLOGY; MFG_PN01: LT3021EDH#PBF; ROHS: Yes
U42 U47 = INA220AIDGST: IC CURRENT/POWER MONITOR 0-26V 3-5.5V MSOP10; AGILE_PN: 315-79035; CAD_APPROVED: Yes; FPLIST: MSOP_10_0P5_3X3,MSOP_10_0P5_3X3_NSP; HEIGHT: 1.10MM; MFG_NAME01: TEXAS INSTRUMENTS; ROHS: Yes
C9 = CAP_NP: CAP CER 100PF 50V 10% X7R 0603; AGILE_PN: 150-75377; ASSY_OPT: DNP; CAD_APPROVED: Yes; FPLIST: CC0603_OV,CC0603,0603_CC; HEIGHT: 0.9652mm; MFG_NAME01: VENKEL COMPANY; MFG_PN01: C0603X7R500-101KNP; ROHS: Yes; Tolerance: 10%; VOLTAGE: 50V
C59 = CAP_POL: CAP ALEL 100uF 25V 20% -- SMD; AGILE_PN: 150-78769; CAD_APPROVED: Yes; HEIGHT: 8MM; MFG_NAME01: LELON ELECTRONICS CORP; MFG_PN01: VE-101M1ETR-0607; ROHS: Yes; Tolerance: 20%; VOLTAGE: 25V
C77 = CAP_POL: CAP ALEL 100uF 25V 20% -- SMD; AGILE_PN: 150-78769; ASSY_OPT: DNP; CAD_APPROVED: Yes; HEIGHT: 8MM; MFG_NAME01: LELON ELECTRONICS CORP; MFG_PN01: VE-101M1ETR-0607; ROHS: Yes; Tolerance: 20%; VOLTAGE: 25V
C79 = CAP_NP: CAP CER 22UF 25V 20% X5R 1210; AGILE_PN: 150-77795; CAD_APPROVED: Yes; FPLIST: CC1210,1210_CC; HEIGHT: 2.8MM; MFG_NAME01: MURATA; MFG_PN01: GRM32ER61E226ME15L; ROHS: Yes; Tolerance: 20%; VOLTAGE: 25V
C80 = CAP_NP: CAP CER 0.1UF 25V 10% X5R 0402; AGILE_PN: 150-78633; CAD_APPROVED: Yes; FPLIST: CC0402_25,CC0402_HD,0402_CC; HEIGHT: 0.55MM; MFG_NAME01: YAGEO AMERICA; MFG_PN01: CC0402KRX5R8BB104; ROHS: Yes; SIGNAL_MODEL: DEFAULT_CAPACITOR_100000pF_2_1; TOL: 10%; Tolerance: 10%; VOLTAGE: 25V
D6 = ZDIODE: DIODE ZNR -- 15V 0.5W SOD123; AGILE_PN: 480-77678; CAD_APPROVED: Yes; Function: Power; HEIGHT: 1.35MM; MFG_NAME01: On Semiconductor; MFG_PN01: MMSZ5245BT1G; ROHS: Yes
D9 D10 = DIODE_SCHTKY: DIODE SCH RECT 1A 20V SMT; AGILE_PN: 480-75997; CAD_APPROVED: Yes; HEIGHT: 1MM; MFG_NAME01: ON SEMICONDUCTOR; ROHS: Yes
D11 = LED: LED GRN SGL 25MA 0603; AGILE_PN: 370-30012; CAD_APPROVED: Yes; HEIGHT: 0.7 MM; MFG_NAME01: DIALIGHT; MFG_PN01: 597-5312-407F; ROHS: Yes
F1 = FUSE_RESETTABLE: FUSE PLYSW 5A HOLD 16V RADIAL; AGILE_PN: 510-77978; CAD_APPROVED: Yes; HEIGHT: 14.3MM; MFG_NAME01: BEL FUSE; MFG_PN01: 0ZRA0500FF1E; ROHS: Yes
J1 = PHONEJACK-3: CON 1 PWR PLUG DIAM 2MM RA TH -- 425H NI 161L; AGILE_PN: 210-77073; CAD_APPROVED: Yes; HEIGHT: 11.3MM; MFG_NAME01: KYCON; MFG_PN01: KLDX-0202-A; ROHS: Yes
J6 = CONN_HDR_2X1: HDR 1X2 TH 100MIL SP 338H SN 100L; AGILE_PN: 210-80102; CAD_APPROVED: Yes; HEIGHT: 8.58MM; MFG_NAME01: SAMTEC; MFG_PN01: TSW-102-07-T-S; ROHS: Yes
Q1 Q14 Q15 Q20 = NPN: TRAN NPN SW 600MA 40V AEC-Q101 SOT23; AGILE_PN: 480-75087; CAD_APPROVED: Yes; HEIGHT: 1.11MM; MFG_NAME01: ON SEMICONDUCTOR; MFG_PN01: MMBT4401LT1G; ROHS: Yes
Q4-Q6 = P_MOS: TRAN PMOS PWR -14A -40V TO-252; AGILE_PN: 480-78831; CAD_APPROVED: Yes; HEIGHT: 2.52 MM; MFG_NAME01: FAIRCHILD; ROHS: Yes
R5 = RES: RES MF 10.0K 1/10W 1% 0603; AGILE_PN: 470-75422; CAD_APPROVED: Yes; FPLIST: RC0603_OV,RC0603,0603_CC; Function: Power; HEIGHT: 0.6MM; MFG_NAME01: KOA SPEER; MFG_PN01: RK73H1JTTD1002F; ROHS: Yes; SIGNAL_MODEL: DEFAULT_RESISTOR_10000OHM_2_1; TOL: 1%; Tolerance: 1%
R94 = RES: RES MF 10.0K 1/10W 1% 0603; AGILE_PN: 470-75422; ASSY_OPT: DNP; CAD_APPROVED: Yes; FPLIST: RC0603_OV,RC0603,0603_CC; HEIGHT: 0.6MM; MFG_NAME01: KOA SPEER; MFG_PN01: RK73H1JTTD1002F; ROHS: Yes; Tolerance: 1%
R102 = RES: RES MF 2.2K 1/10W 5% 0603; AGILE_PN: 470-75399; CAD_APPROVED: Yes; FPLIST: RC0603_OV,RC0603,0603_CC; HEIGHT: 0.55MM; MFG_NAME01: VENKEL COMPANY; MFG_PN01: CR0603-10W-222JT; ROHS: Yes; Tolerance: 5%
SW4 = SW_TACT-SPST-2_SM1: SW SPST PB NO RA 12V 50MA TH; AGILE_PN: 510-77298; CAD_APPROVED: Yes; HEIGHT: 7MM; MFG_NAME01: E SWITCH; ROHS: Yes
U3 = MAX811: IC VOLTAGE MONITOR 4PIN SOT143; AGILE_PN: 312-75604; CAD_APPROVED: YES; HEIGHT: 1.22 MM; MFG_NAME01: MAXIM; MFG_PN01: MAX811SEUS+; ROHS: Yes

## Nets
1V2_RST_n: Q15.3(COLLECTOR) R200.2 ; also on sheet 5 16
1V8_RST_n: Q14.3(COLLECTOR) R197.2 ; also on sheet 6 7
12V: C91.1 C92.1 C96.1 C99.1 C100.2 C101.1 C102.1 C104.2 C408.2 C635.1 C636.1 C637.2 C654.1 C655.1 C656.2 J9.2 J18.3 J23.1 J26.1 R100.2 R146.1 R241.1 R242.1 R446.1 U22.5(VIN1) U22.6(VIN2) U22.7(VIN3) U28.5(VIN1) U28.6(VIN2) U28.7(VIN3) U29.5(VIN1) U29.6(VIN2) U29.7(VIN3) U45.5(VIN1) U45.6(VIN2) U45.7(VIN3) U49.5(VIN1) U49.6(VIN2) U49.7(VIN3) ; also on sheet 23
12V_DECT: C9.1 D6.C(CATHODE) D9.A F1.2 J18.1 J23.3 J26.3 Q6.4(D2) R231.1 R232.2 R247.1 ; also on sheet 23
12V_SUP: D9.C D10.C R97.2 R236.2
AVDD_CGA1: Q21.3(S2) R16.1 R17.1 R193.1 R194.2 R197.1 ; also on sheet 6 7 8 9 11 12 13 24
GND: C6.2 C7.1 C9.2 C59.2 C77.2 C79.2 C80.2 C84.1 C85.2 C86.2 C88.2 C89.2 C90.2 C91.2 C92.2 C93.2 C94.2 C95.2 C96.2 C97.2 C98.2 C99.2 C100.1 C101.2 C102.2 C103.2 C104.1 C105.2 C107.2 C108.2 C118.2 C127.2 C288.1 C289.1 C300.2 C302.2 C303.2 C304.2 C305.2 C306.2 C307.2 C308.2 C309.2 C313.2 C314.2 C318.2 C319.2 C321.2 C322.2 C324.2 C325.2 C326.2 C327.2 C370.2 C386.1 C408.1 C428.2 C439.2 C440.2 C443.2 C455.2 C456.2 C457.2 C458.2 C463.2 C469.2 C477.2 C478.2 C480.2 C611.2 C622.2 C623.2 C624.2 C626.2 C627.2 C628.2 C630.2 C631.2 C634.2 C635.2 C636.2 C637.1 C638.2 C639.2 C643.2 C648.2 C649.2 C650.2 C653.2 C654.2 C655.2 C656.1 C657.2 C658.2 D6.A(ANODE) D11.C(CATHODE) J1.2 J6.2 J9.1 J9.3 J12.2 P2.4(GND7) P2.9(GND1) P2.15(GND2) P2.18(GND8) P2.21(GND3) P2.26(GND9) P2.27(GND4) P2.29(GND5) P2.34(GND10) P2.35(GND6) P2.40(GND11) P2.50(GND12) P3.4(GND7) P3.9(GND1) P3.15(GND2) P3.18(GND8) P3.21(GND3) P3.26(GND9) P3.27(GND4) P3.29(GND5) P3.34(GND10) P3.35(GND6) P3.40(GND11) P3.50(GND12) Q19.1(S2) Q19.3(S2) Q20.2(EMITTER) Q22.1(S2) Q22.3(S2) R5.2 R94.1 R104.1 R107.2 R109.2 R111.2 R114.2 R115.2 R117.2 R122.2 R126.2 R128.2 R129.2 R134.2 R147.1 R148.2 R151.2 R230.2 R234.2 R240.1 R248.1 R249.2 R258.1 R320.2 R327.2 R334.2 R335.2 R345.2 R348.2 R350.2 R352.2 R355.2 R358.2 R359.2 R361.2 R399.2 R433.2 R435.2 R437.1 R439.2 R440.2 R441.2 R448.1 R449.1 R450.1 R470.2 R472.1 R473.2 R474.2 R475.2 R476.2 SW4.2 SW4.3 SW4.4 U3.1(GND) U19.25(GND) U22.1(SYNC) U22.8(PGND1) U22.9(PGND2) U22.10(PGND3) U22.11(GND1) U22.12(GND2) U22.13(GND3) U22.14(GND4) U22.25(GND5) U22.26(GND6) U22.27(GND7) U22.28(GND8) U22.29(GND9) U26.8(AGND) U26.10(PGND) U26.17(PAD) U28.1(SYNC) U28.8(PGND1) U28.9(PGND2) U28.10(PGND3) U28.11(GND1) U28.12(GND2) U28.13(GND3) U28.14(GND4) U28.25(GND5) U28.26(GND6) U28.27(GND7) U28.28(GND8) U28.29(GND9) U29.1(SYNC) U29.8(PGND1) U29.9(PGND2) U29.10(PGND3) U29.11(GND1) U29.12(GND2) U29.13(GND3) U29.14(GND4) U29.25(GND5) U29.26(GND6) U29.27(GND7) U29.28(GND8) U29.29(GND9) U42.7(GND) U43.16(GND) U45.1(SYNC) U45.8(PGND1) U45.9(PGND2) U45.10(PGND3) U45.11(GND1) U45.12(GND2) U45.13(GND3) U45.14(GND4) U45.25(GND5) U45.26(GND6) U45.27(GND7) U45.28(GND8) U45.29(GND9) U47.7(GND) U49.1(SYNC) U49.8(PGND1) U49.9(PGND2) U49.10(PGND3) U49.11(GND1) U49.12(GND2) U49.13(GND3) U49.14(GND4) U49.25(GND5) U49.26(GND6) U49.27(GND7) U49.28(GND8) U49.29(GND9) Y5.2 Y5.4 ; also on sheet 5 6 7 8 9 10 11 12 13 14 15 16 17 22 23 24
ADP_12V: C59.1 C77.1 C79.1 C80.1 Q5.4(D2) Q6.3(S) R100.1 R102.1 R447.1 U47.8(VBUS)
AQR105_VA12: R200.1 ; also on sheet 9 11 16 17 23
CPU_RST_REQ: Q1.2(EMITTER) R17.2 ; also on sheet 8
DCDC1_3V3: C95.1 C106.1 C107.1 C428.1 C439.1 C440.1 C443.1 C455.1 L19.2 P3.2(3.3V_1) P3.24(+3.3Vaux) P3.39(Reserved4) P3.41(Reserved5) P3.52(3.3V_2) R149.1 U28.22(BIAS) ; also on sheet 15
DCDC2_3V3: C6.1 C84.2 C97.1 C108.1 C109.1 C118.1 C127.1 C370.1 C386.2 C469.1 C477.1 C611.1 D15.A(ANODE) D16.A(ANODE) D17.A(ANODE) L20.2 L25.1 L26.2 Q7.1(S2) Q23.3(DRAIN) R8.1 R15.2 R118.1 R119.2 R120.1 R125.2 R152.1 R246.1 R451.1 U3.4(VCC) U22.22(BIAS) U26.12(IN1) U26.14(IN2) U29.22(BIAS) U42.6(VCC) U43.1(CLK_EN) U43.9(VDD1) U43.10(VDD2) U43.15(VDD3) U47.6(VCC) ; also on sheet 6 7 8 10 11 13 14 15 23 24
DCDC2_3V3_PG: U29.23(PG) ; also on sheet 24
DCDC_1V0: R326.2 R444.2 ; also on sheet 11
DCDC_1V0_SUP: C87.1 C90.1 C93.1 C94.1 L18.2 R127.1 R326.1 R445.2 U42.8(VBUS)
EVDD: Q7.3(S2) Q21.1(S2) R240.2 ; also on sheet 7 11
GPIO3_0_WAKE_L: P2.1(WAKE#) ; also on sheet 8 9
GPIO3_1_CLKREQ_L: P2.7(CLKREQ#) ; also on sheet 9
GPIO3_2_WAKE_L: P3.1(WAKE#) ; also on sheet 9
GPIO3_3_CLKREQ_L: P3.7(CLKREQ#) ; also on sheet 9
I2C1_SCL: R418.1 ; also on sheet 8 13 24
I2C1_SDA: R417.1 ; also on sheet 8 13 24
I2C2_SCL: R415.1 U42.5(SCL) U47.5(SCL) ; also on sheet 8 13
I2C2_SDA: R416.1 U42.4(SDA) U47.4(SDA) ; also on sheet 8 13
LANEA_RX_N: P3.23(PERn0) ; also on sheet 9
LANEA_RX_P: P3.25(PERp0) ; also on sheet 9
LANEA_TX_N: P3.31(PETn0) ; also on sheet 9
LANEA_TX_P: P3.33(PETp0) ; also on sheet 9
LANEC_RX_N: P2.23(PERn0) ; also on sheet 9
LANEC_RX_P: P2.25(PERp0) ; also on sheet 9
LANEC_TX_N: P2.31(PETn0) ; also on sheet 9
LANEC_TX_P: P2.33(PETp0) ; also on sheet 9
LDO_1V0: C98.1 R137.2 U26.3(OUT1) U26.4(OUT2) ; also on sheet 9 11
MPCIE1_CLK+: P3.13(REFCLK+) R351.2 R352.1
MPCIE1_CLK-: P3.11(REFCLK-) R357.2 R358.1
MPCIE2_CLK+: P2.13(REFCLK+) R333.2 R334.1
MPCIE2_CLK-: P2.11(REFCLK-) R347.2 R348.1
PCIE_3V3: C300.1 C306.1 C307.1 C308.1 P2.2(3.3V_1) P2.24(+3.3Vaux) P2.39(Reserved4) P2.41(Reserved5) P2.52(3.3V_2) Q23.2(SOURCE) R246.2 R249.1
POE_12V: D10.A Q4.4(D2) R235.2 ; also on sheet 22
RESET: P2.22(PERST#) P3.22(PERST#) Q14.2(EMITTER) Q15.2(EMITTER) R15.1 U3.2(~{RESET}) ; also on sheet 7 8 14 15
SD_CLK1_N: R113.2 R114.1 ; also on sheet 9
SD_CLK1_P: R110.2 R111.1 ; also on sheet 9
SD_CLK2_N: R121.2 R122.1 ; also on sheet 9
SD_CLK2_P: R116.2 R117.1 ; also on sheet 9
SDHC_VS: R266.1 ; also on sheet 8
SYS_REFCLK_N: R108.2 R109.1 ; also on sheet 8
SYS_REFCLK_P: R106.2 R107.1 ; also on sheet 8
VCORE_EN: R320.1 R327.1 U22.4(EN/UV) U26.9(~{SHDN}) ; also on sheet 24
VPA: C622.1 C623.1 C624.1 C630.1 C632.1 C634.1 C639.1 C643.1 L30.2 P2.45(Reserved7) P2.47(Reserved8) P2.49(Reserved9) P2.51(Reserved10) R434.1 U45.22(BIAS)
VPA_PCIE2: C626.1 C627.1 C628.1 C648.1 C649.1 C651.1 C653.1 C658.1 L31.2 P3.45(Reserved7) P3.47(Reserved8) P3.49(Reserved9) P3.51(Reserved10) R469.1 U49.22(BIAS)
VR500_1V5: C321.1 C322.1 C324.1 C326.1 C456.1 C457.1 C458.1 C463.1 P2.6(1.5V_1) P2.28(1.5V_2) P2.48(1.5V_3) P3.6(1.5V_1) P3.28(1.5V_2) P3.48(1.5V_3) ; also on sheet 24
N24133241: F1.1 J1.1 R5.1
N24137908: C89.1 U22.21(INTVCC)
N24137912: C405.2 L18.1 U22.15(SW1) U22.16(SW2) U22.17(SW3) U22.18(SW4) U22.19(SW5)
N24137946: C405.1 U22.20(BST)
N24137962: C87.2 R127.2 R128.1 U22.24(FB)
N24138040: R129.1 U22.3(RT)
N24138143: C88.1 U22.2(TR/SS)
N24145679: C302.1 C305.1 C309.1 C314.1 C318.1 C325.1 C327.1 L26.1 R105.1 U19.10(VDDO4) U19.15(VDDO3) U19.18(VDDO2) U19.21(VDDO1) U19.23(VDDO0)
N24145732: C313.1 C319.1 R263.2 U19.5(VDDA)
N24145752: C303.1 C304.1 L25.2 R263.1 U19.22(VDDD)
N24151368: C86.1 R112.2 U19.4(XIN/REF) Y5.1
N24151377: C85.1 R112.1 U19.3(XOUT) Y5.3
N24157795: R104.2 R105.2 U19.24(OUT0_SEL_I2CB)
N24157798: J12.3 R125.1 R126.1 U19.8(SEL1/SDA)
N24157984: R106.1 U19.20(OUT1_P)
N24157991: R108.1 U19.19(OUT1_N)
N24158001: R113.1 U19.16(OUT2_N)
N24158003: R110.1 U19.17(OUT2_P)
N24158101: R116.1 U19.14(OUT3_P)
N24158103: R121.1 U19.13(OUT3_N)
N24158105: R124.1 U19.12(OUT4_N)
N24158107: R123.1 U19.11(OUT4_P)
N24158224: R123.2 R345.1 U43.3(CLK0)
N24158233: R124.2 R350.1 U43.4(nCLK0)
N24158614: J12.1 R115.1 R119.1 U19.9(SEL0/SCL)
N24164336: R355.1 U43.8(IREF)
N24164341: R335.1 U43.2(CLK_SEL)
N24164581: R333.1 U43.14(Q0)
N24164584: R347.1 U43.13(nQ0)
N24164587: R351.1 U43.12(Q1)
N24164590: R357.1 U43.11(nQ1)
N24506779: C478.1 U28.21(INTVCC)
N24506783: C474.2 L19.1 U28.15(SW1) U28.16(SW2) U28.17(SW3) U28.18(SW4) U28.19(SW5)
N24506809: C474.1 U28.20(BST)
N24506829: C106.2 R148.1 R149.2 U28.24(FB)
N24506871: R359.1 U28.3(RT)
N24506911: R145.1 R147.2 U28.4(EN/UV)
N24506929: C105.1 U28.2(TR/SS)
N24509763: C480.1 U29.21(INTVCC)
N24509767: C481.2 L20.1 U29.15(SW1) U29.16(SW2) U29.17(SW3) U29.18(SW4) U29.19(SW5)
N24509789: C481.1 U29.20(BST)
N24509805: C109.2 R151.1 R152.2 U29.24(FB)
N24509853: R361.1 U29.3(RT)
N24509885: R146.2 U29.4(EN/UV)
N24509913: C103.1 U29.2(TR/SS)
N24514524: TP12.1(Pin1) U22.23(PG)
N24515056: J18.2 R145.2
N24551325: J6.1 R9.1 SW4.1
N24551347: C7.2 Q1.3(COLLECTOR) R8.2 R9.2 U3.3(~{MR})
N24652945: Q4.1(G) Q5.1(G) Q20.3(COLLECTOR) R236.1
N24653996: Q19.4(G2) R230.1 R231.2
N24654004: Q6.1(G) Q19.5(D2-2) Q19.6(D2-1) R97.1
N24665133: Q21.5(D2-2) Q21.6(D2-1) Q21.7(D2-2) Q21.8(D2-1)
N24674533: C288.2 Q7.2(G2) Q7.4(G2) Q22.4(G2) Q22.7(D2-2) Q22.8(D2-1) R241.2
N24674544: C289.2 Q21.2(G2) Q21.4(G2) Q22.5(D2-2) Q22.6(D2-1) R242.2
N24675233: Q22.2(G2) R258.2 R266.2
N24678302: Q23.1(GATE) R247.2 R248.2
N24861043: Q1.1(BASE) R16.2
N24876902: Q14.1(BASE) R194.1
N24877168: Q15.1(BASE) R193.2
N24996629: Q4.3(S) Q5.3(S) R94.2
N25072149: R118.2 U19.6(CLKSEL)
N25118599: Q19.7(D2-2) Q19.8(D2-1) Q20.1(BASE) R235.1
N25120670: Q19.2(G2) R232.1 R234.1
N25141555: D15.C(CATHODE) R399.1
N25212963: R134.1 R137.1 U26.7(SENSE/ADJ)
N25462949: R120.2 U19.7(SD/~{OE})
N25493237: TP17.1(Pin1) U28.23(PG)
N25622344: C644.2 R445.1 U42.10(VIN+)
N25622365: C644.1 R444.1 U42.9(VIN-)
N25675358: Q7.5(D2-2) Q7.6(D2-1) Q7.7(D2-2) Q7.8(D2-1)
N25696806: D11.A(ANODE) R102.2
N26607524: D17.C(CATHODE) R397.1
N26607549: P2.44(LED_WLAN#) R398.1
N26607619: D16.C(CATHODE) R398.2
N26607860: P3.44(LED_WLAN#) R397.2
N26620998: P2.30(SMB_CLK) R415.2
N26621001: P2.32(SMB_DATA) R416.2
N26621044: P3.30(SMB_CLK) R418.2
N26621047: P3.32(SMB_DATA) R417.2
N26669713: C638.1 U45.21(INTVCC)
N26669717: C633.2 L30.1 U45.15(SW1) U45.16(SW2) U45.17(SW3) U45.18(SW4) U45.19(SW5)
N26669739: C633.1 U45.20(BST)
N26669755: C632.2 J25.1(A1) J25.3(A2) J25.5(A3) J25.7(A4) R434.2 U45.24(FB)
N26669803: R435.1 U45.3(RT)
N26669831: R436.1 R437.2 U45.4(EN/UV)
N26669847: C631.1 U45.2(TR/SS)
N26670020: TP58.1(Pin1) U45.23(PG)
N26671814: J25.8(B4) R433.1
N26671819: J25.6(B3) R439.1
N26671824: J25.4(B2) R441.1
N26671827: J25.2(B1) R440.1
N26683821: J23.2 R436.2
N26711184: C645.1 R447.2 U47.10(VIN+)
N26711194: C645.2 R446.2 U47.9(VIN-)
N26711585: R448.2 U47.1(A1)
N26711588: R449.2 U47.2(A0)
N26712218: R450.2 U42.1(A1)
N26712221: R451.2 U42.2(A0)
N26901042: C657.1 U49.21(INTVCC)
N26901046: C652.2 L31.1 U49.15(SW1) U49.16(SW2) U49.17(SW3) U49.18(SW4) U49.19(SW5)
N26901068: C652.1 U49.20(BST)
N26901080: C651.2 J27.1(A1) J27.3(A2) J27.5(A3) J27.7(A4) R469.2 U49.24(FB)
N26901130: R470.1 U49.3(RT)
N26901158: R471.1 R472.2 U49.4(EN/UV)
N26901172: C650.1 U49.2(TR/SS)
N26901338: TP62.1(Pin1) U49.23(PG)
N26901371: J26.2 R471.2
N26901409: J27.8(B4) R473.1
N26901413: J27.6(B3) R476.1
N26901417: J27.4(B2) R475.1
N26901419: J27.2(B1) R474.1

Not connected (* = marked no-connect by the designer): J1 3*; P2 3(Reserved1)* 5(Reserved2)* 8(UIM_PWR)* 10(UIM_DATA)* 12(UIM_CLK)* 14(UIM_RESET)* 16(UIM_VPP)* 17(Reserved/UIM_C8)* 19(Reserved/UIM_C4)* 20(W_DISABLE#)* 36(USB_D-)* 37(Reserved3)* 38(USB_D+)* 42(LED_WWAN#)* 43(Reserved6)* 46(LED_WPAN#)*; P3 3(Reserved1)* 5(Reserved2)* 8(UIM_PWR)* 10(UIM_DATA)* 12(UIM_CLK)* 14(UIM_RESET)* 16(UIM_VPP)* 17(Reserved/UIM_C8)* 19(Reserved/UIM_C4)* 20(W_DISABLE#)* 36(USB_D-)* 37(Reserved3)* 38(USB_D+)* 42(LED_WWAN#)* 43(Reserved6)* 46(LED_WPAN#)*; U19 1(CLKIN_P)* 2(CLKIN_N)*; U26 1(NC1)* 2(NC2)* 5(NC3)* 6(NC4)* 11(NC5)* 13(NC6)* 15(NC7)* 16(NC8)*; U42 3(NC)*; U43 5(CLK1)* 6(NC1)* 7(NC2)*; U47 3(NC)*

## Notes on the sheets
sheet 18
- MINI-PCIe 1
  WiFi 1 LED on Enclosure
- Default shunt 1-2
- IND PWR 2.2UH@100KHZ
   9.2A 20% AEC-Q200
- Card PN
- PA Vol
- Power
- Header
- CUS238
- 3.5V
- 5.74W
- 5-6
- CUS239
- 5V
- 11.2W
- 1-2
- Default shunt 7-8
- CUS240
- 3.3V
- 5.28W
- 7-8
- CUS260
- 4.5V
- 9W
- 3-4
- WiFi 1 LED on enclosure
- If the POE power is not sufficient
  DNP R291 and mount Q23 to shut
  down one PCIE power
- Default shunt 2-3
- IND PWR 2.2UH@100KHZ
   9.2A 20% AEC-Q200
- Card PN
- PA Vol
- Power
- Header
- CUS238
- 3.5V
- 5.74W
- 5-6
- Use DCDC2_3V3 is for rounting convenience
- CUS239
- 5V
- 11.2W
- 1-2
- Default shunt 7-8
- CUS240
- 3.3V
- 5.28W
- 7-8
- CUS260
- 4.5V
- 9W
- 3-4
- WiFi 2 LED on enclosure
- MINI-PCIe 2
  If only one card, should be
  inserted on PCIe 2 slot
sheet 20
- DCDC2_3V3 always on to VR500+
  RGMII PHY+1-PCIe+board peripheral
   parts
- DCDC1_3V3 to SGMII PHY+1-PCIe
  should be shut down when
  External adapter not presented
- IND PWR 2.2UH@100KHZ
   9.2A 20% AEC-Q200
- Enable VR500
- IND PWR 2.2UH@100KHZ
   9.2A 20% AEC-Q200
- Always ON to CPU Core
  at CPU power sequence 2
- VR500_3V3 from VR500 LDO2
  to enable CORE before VR500
  GVDD ramp up
- LT8812 Minimum voltage
  is 0.97V
- IND PWR 2.2UH@100KHZ
   9.2A 20% AEC-Q200
- C559 2200 PF to
  set the ramp
  up within 1ms
- I2C2 ADDR:1000001
  0X41
- SDHC_VS set 0 to enable 3.3V SD/MMC
  Set 1 to enable 1.8V SD/MMC
- S1VDD power at
  CPU power  sequence 2
  100mA
- VR500_3V3 from VR500 LDO2
  to enable CORE before VR500
  GVDD ramp up
sheet 21
- Casecade PMOS to prevent
   adapter current flow backward
  or POE current conduct through
  body diode
- NOTES: External Power adapter
  set higher priority than POE,
  so only external power adapter
  is not presented, then PMOS Q15 is
  permited to conduct the POE power
- I2C2 ADDR:1000000
  0X40
- 12V/5A
- 2512 Package to
   use choke for FCC
- RESET LEVEL SHIFT
- NOR/NAND/SPI FLASH
- DDR/AQR105
- POWER ON RESET
- RESET eMMC/CPU POR
  RTL8211/PCIe
- GVDD Power Good Signal From VR500
- RESET
  REMOTE HEADER
